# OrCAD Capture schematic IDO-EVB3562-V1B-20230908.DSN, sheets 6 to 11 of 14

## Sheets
6 P16.VI-Camera_MIPI_CSI: size A3; title: IDO-SBC3566-V1B; note: VI-Camera_MIPI_CSI
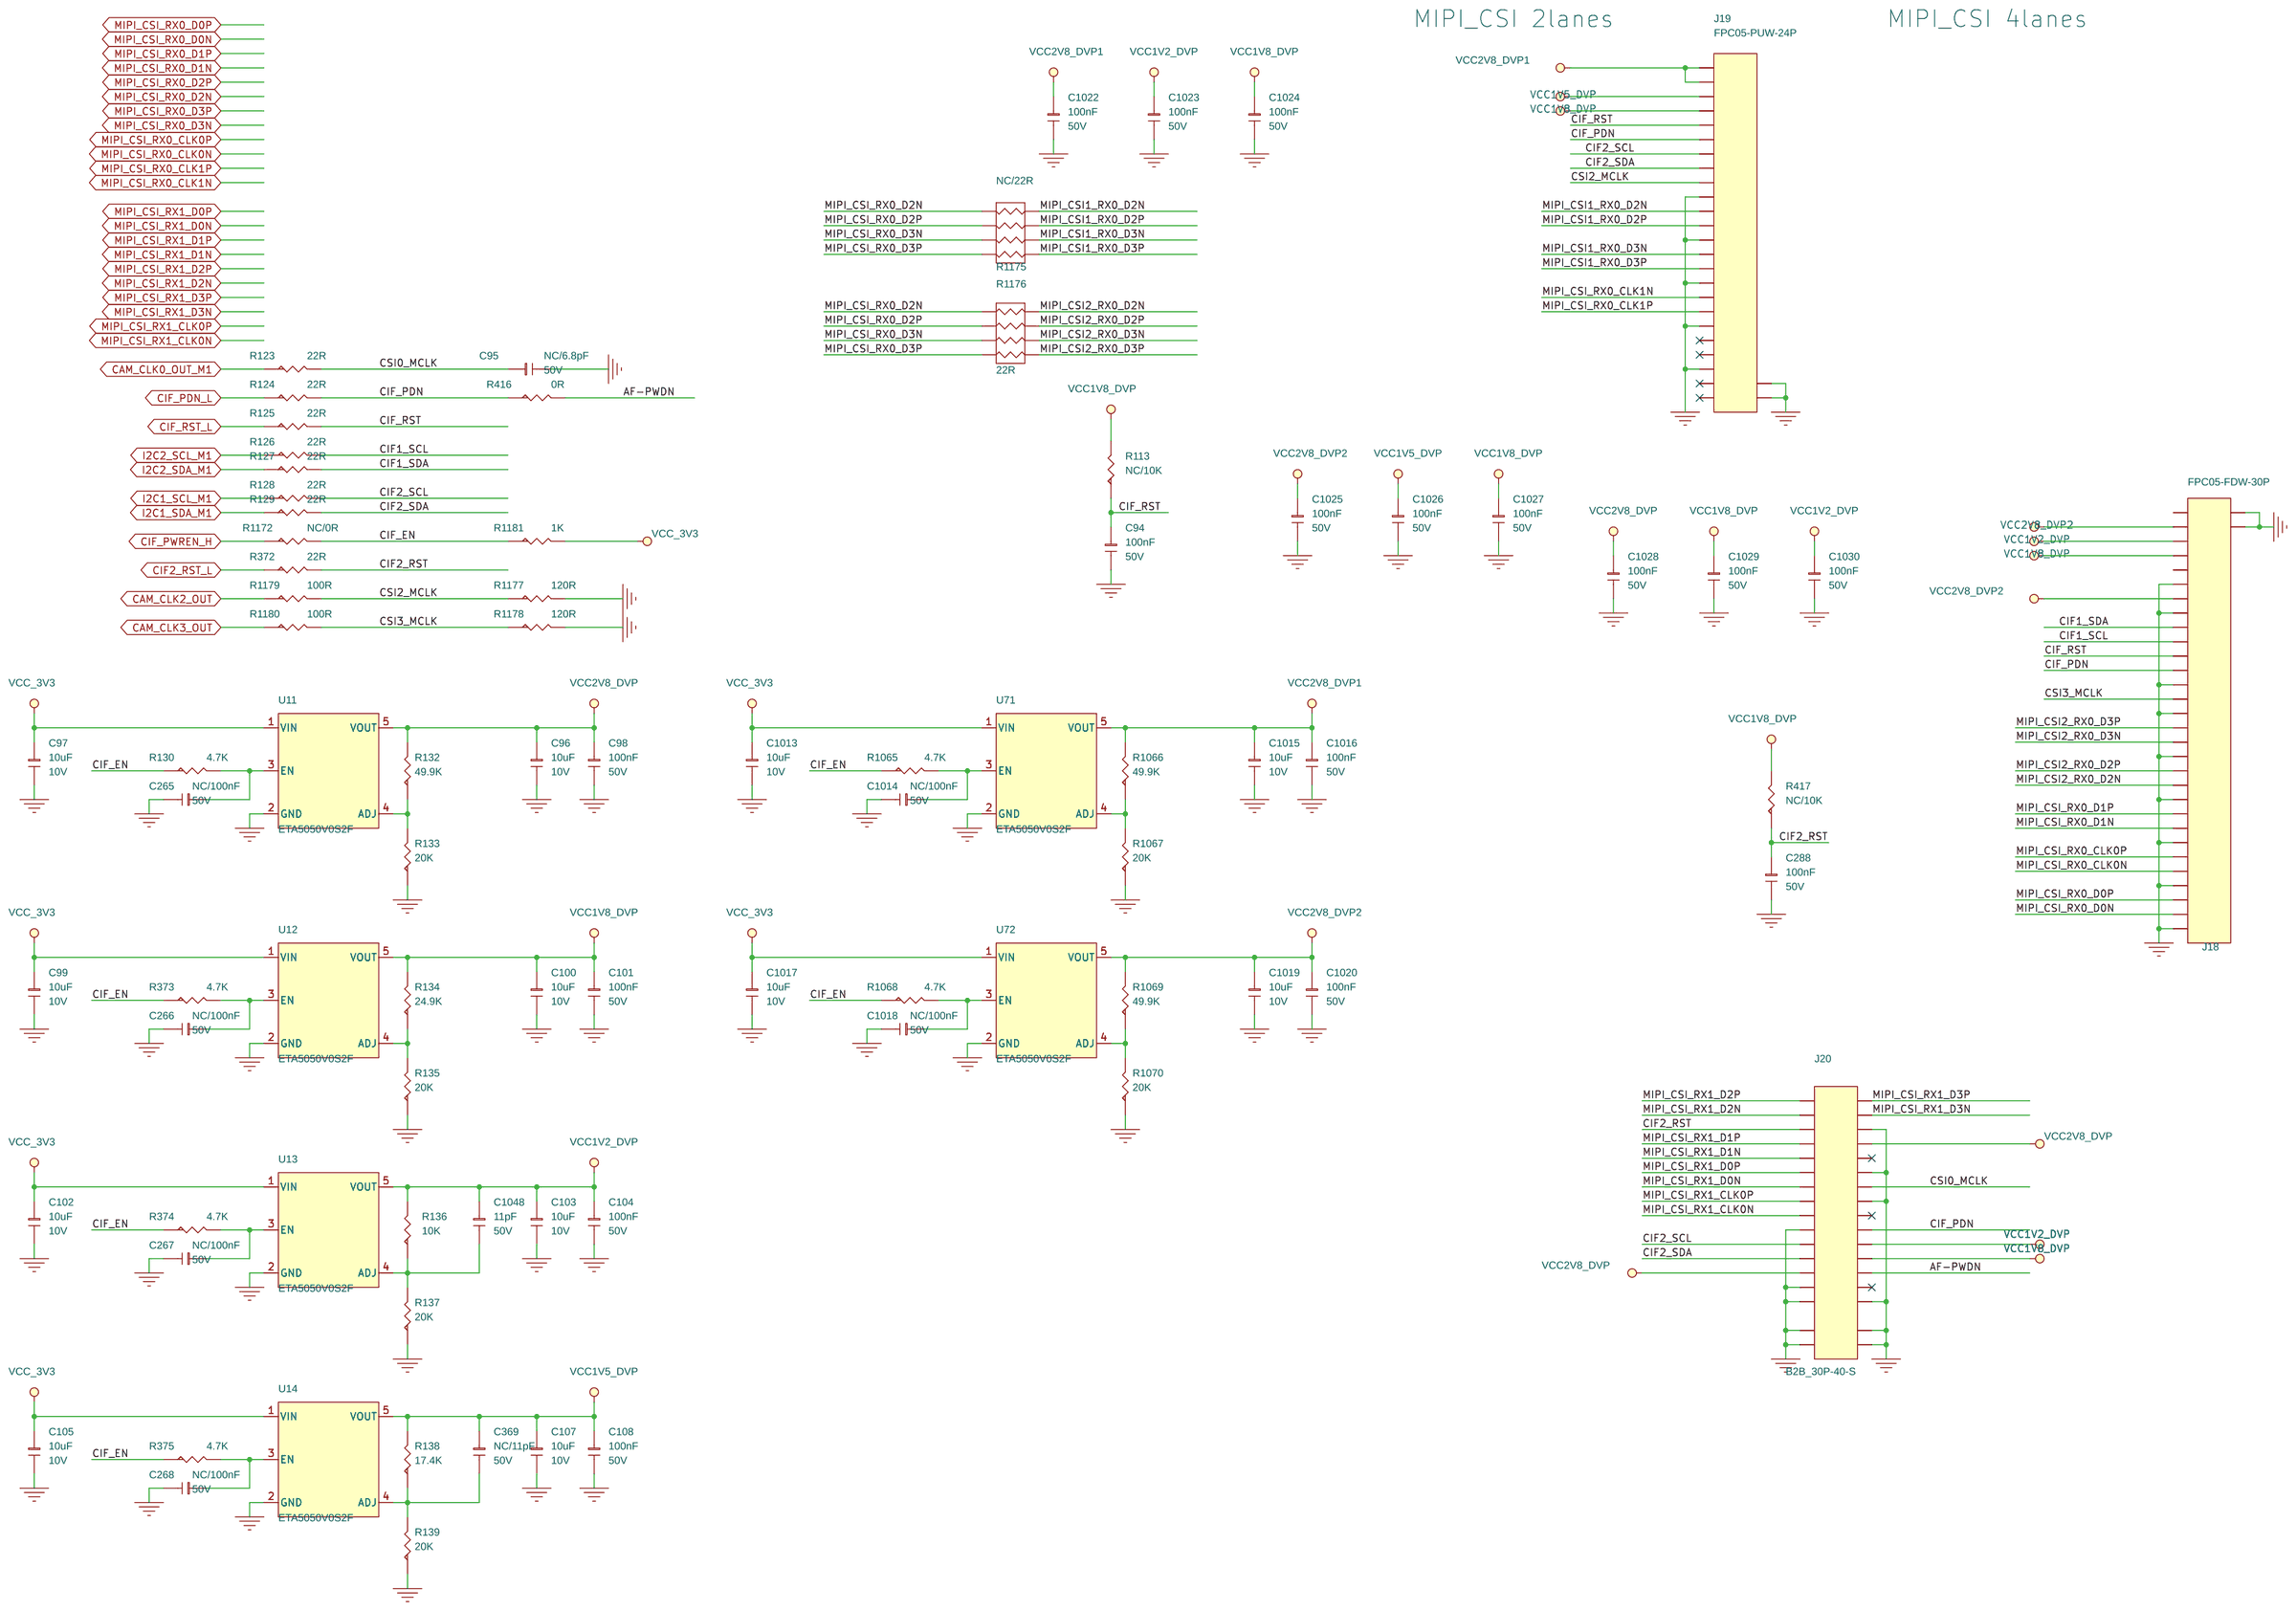
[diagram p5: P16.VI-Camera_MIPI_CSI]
7 P17.Ethernet2-PCIE: size A3; title: IDO-EVB3588-V1; note: Ethernet2-PCIE
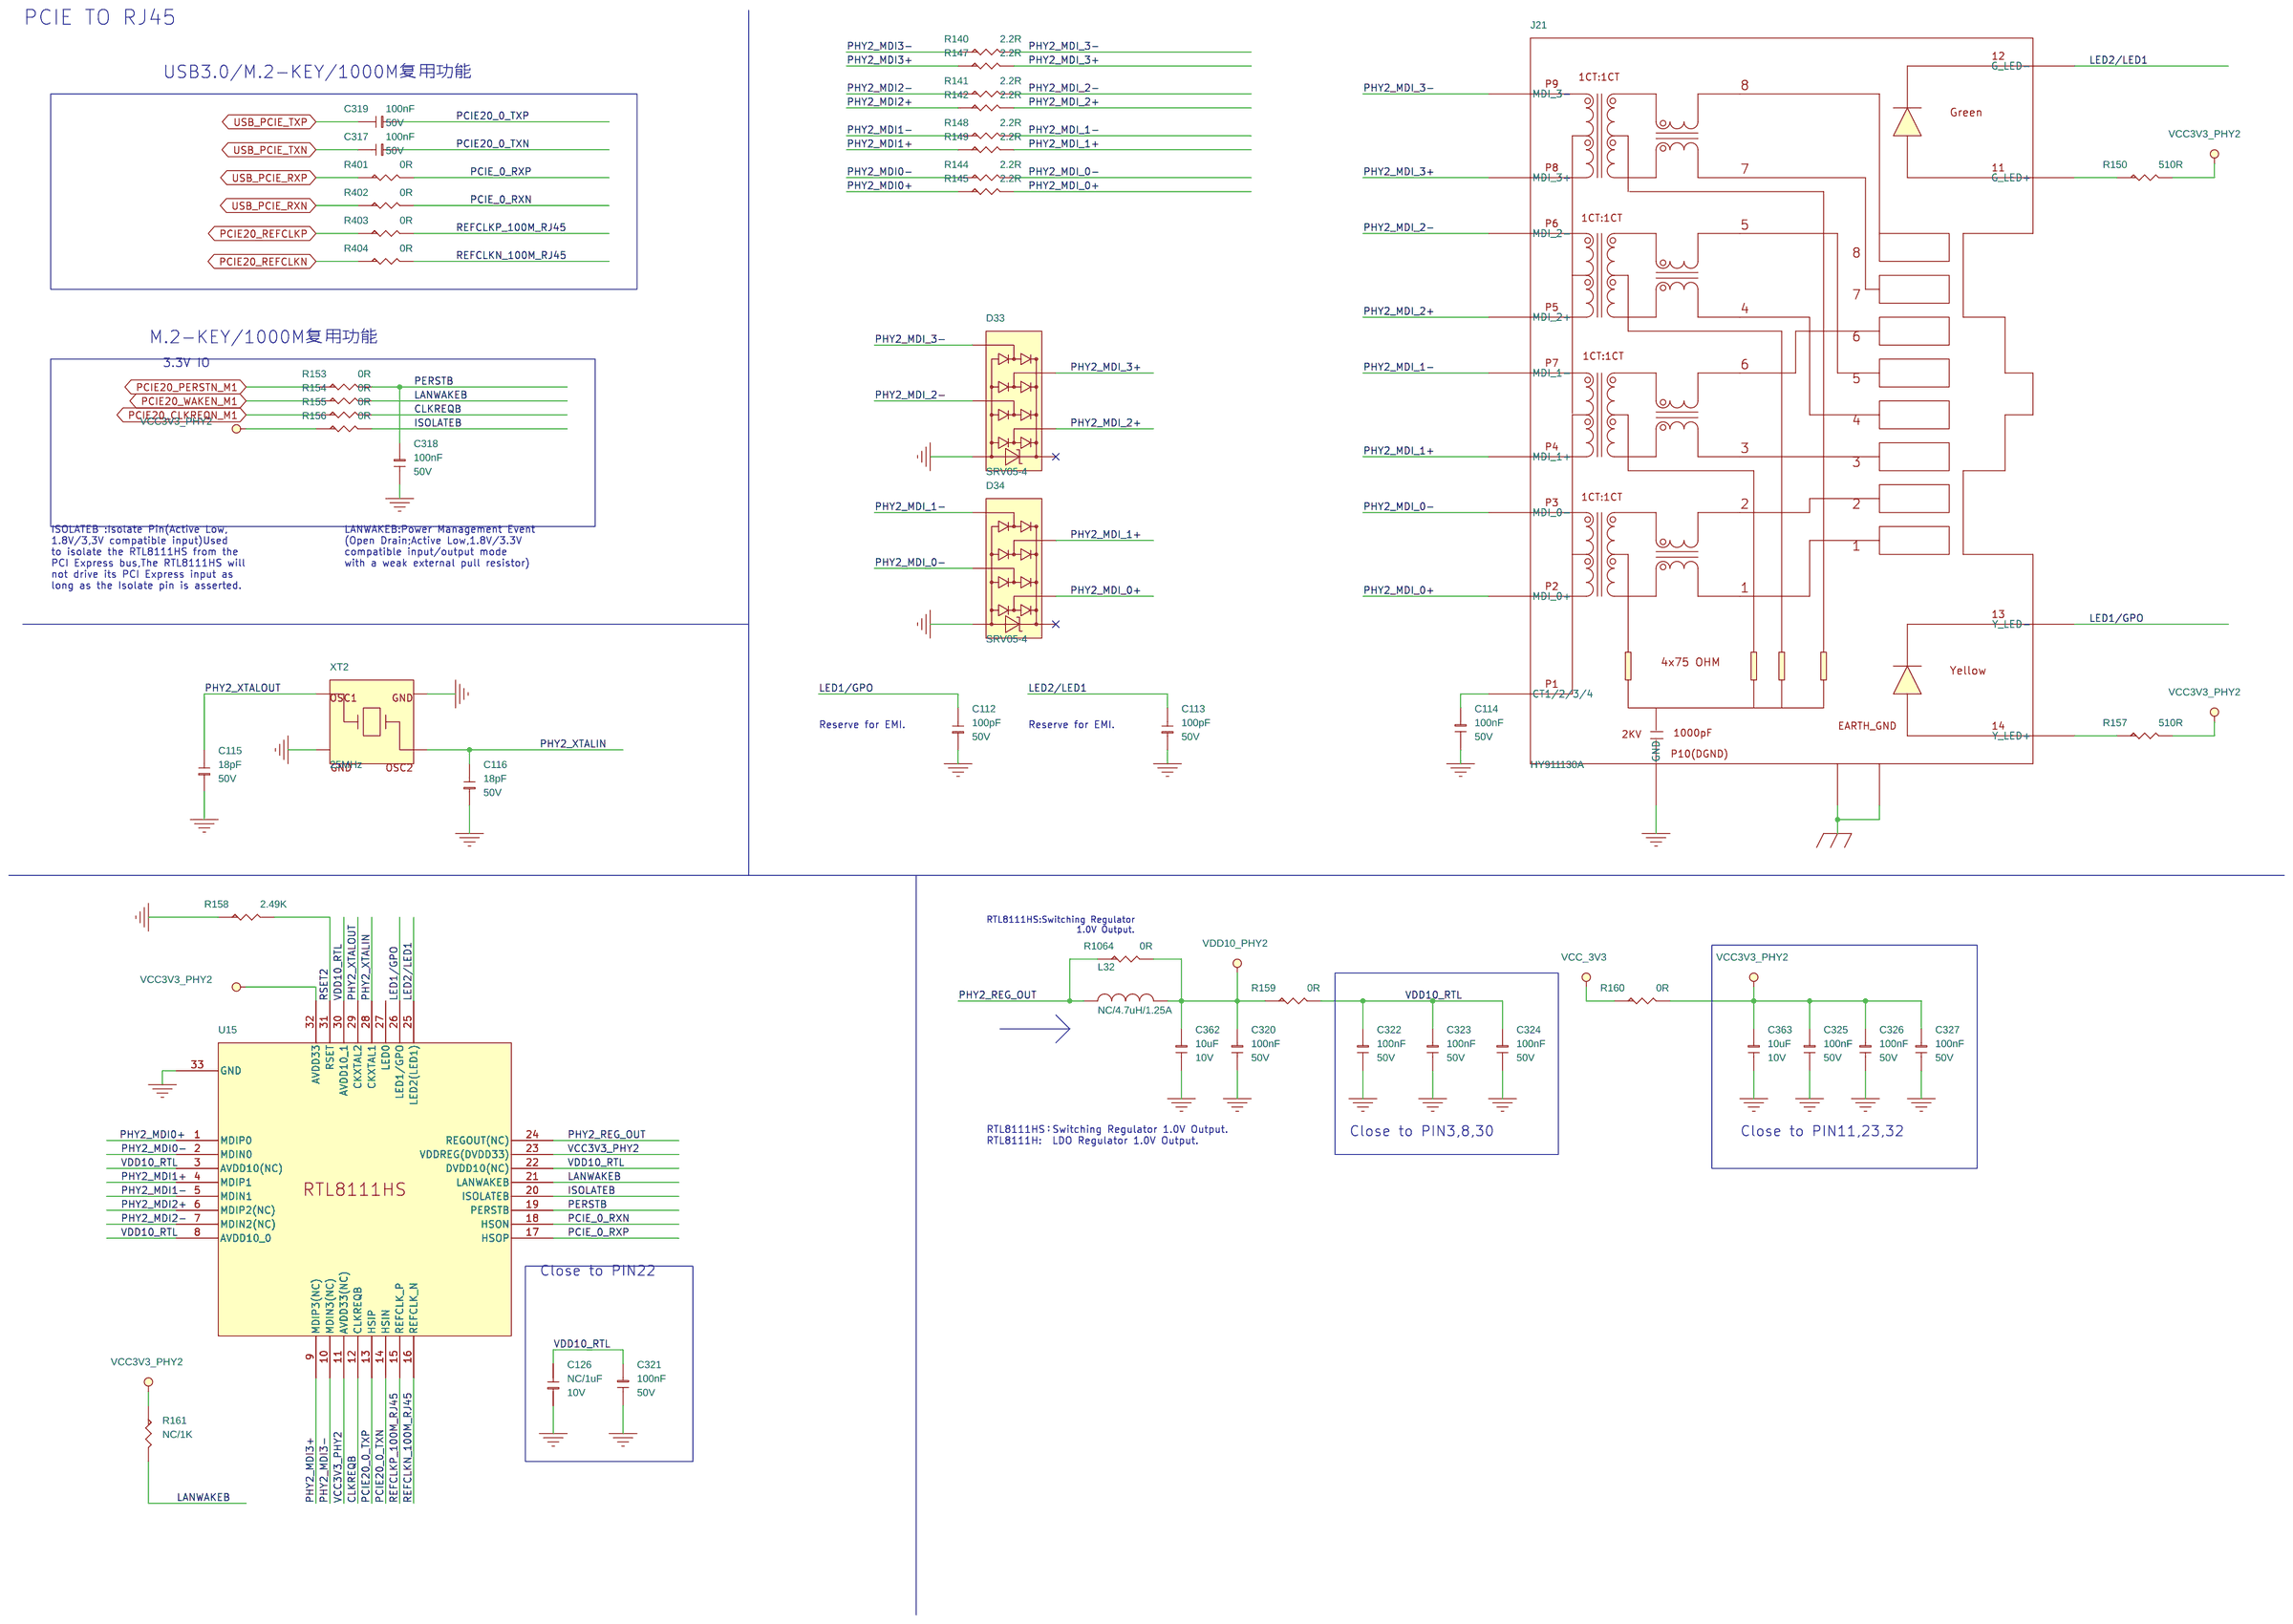
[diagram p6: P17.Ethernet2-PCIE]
8 P18. Ethernet-GEPHY_RGMII: size A2; title: IDO-SBC3566-V1B; note: Ethernet-GEPHY_RGMII
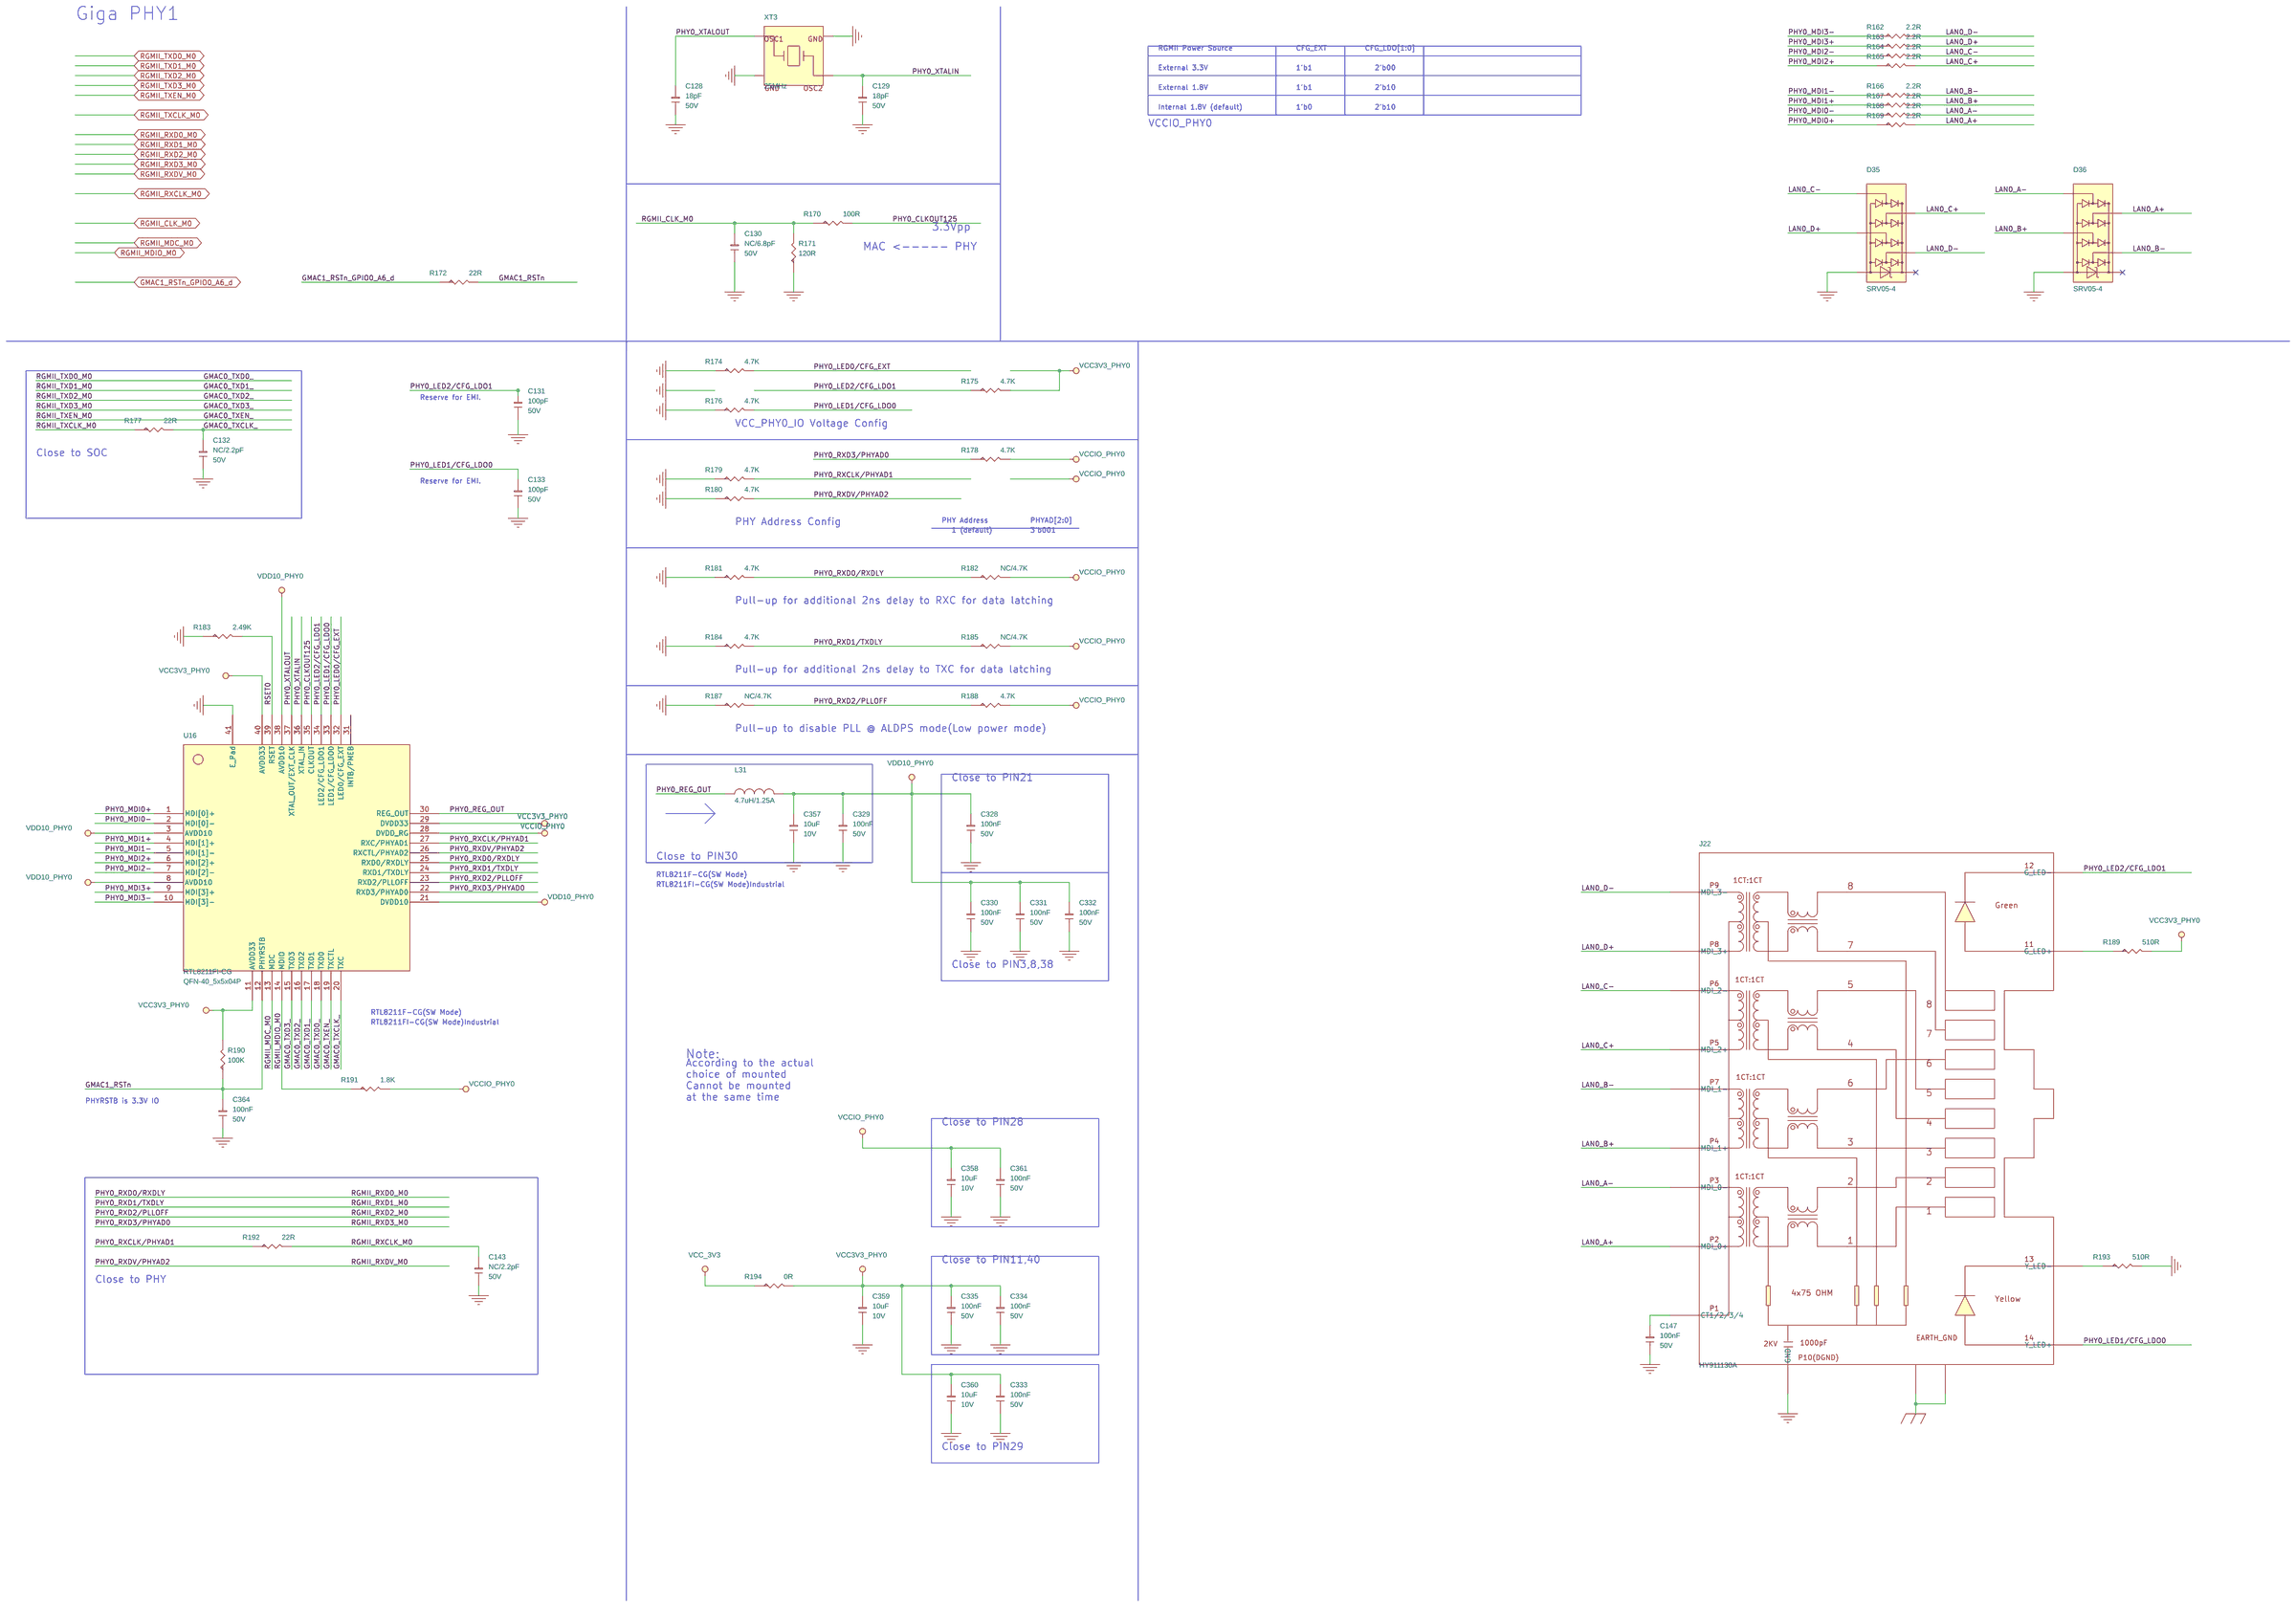
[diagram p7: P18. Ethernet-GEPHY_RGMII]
9 P30.IO/ADC: size A4; title: IDO-SBC3566-V1B; note: TP_Connector-COF/Backlight
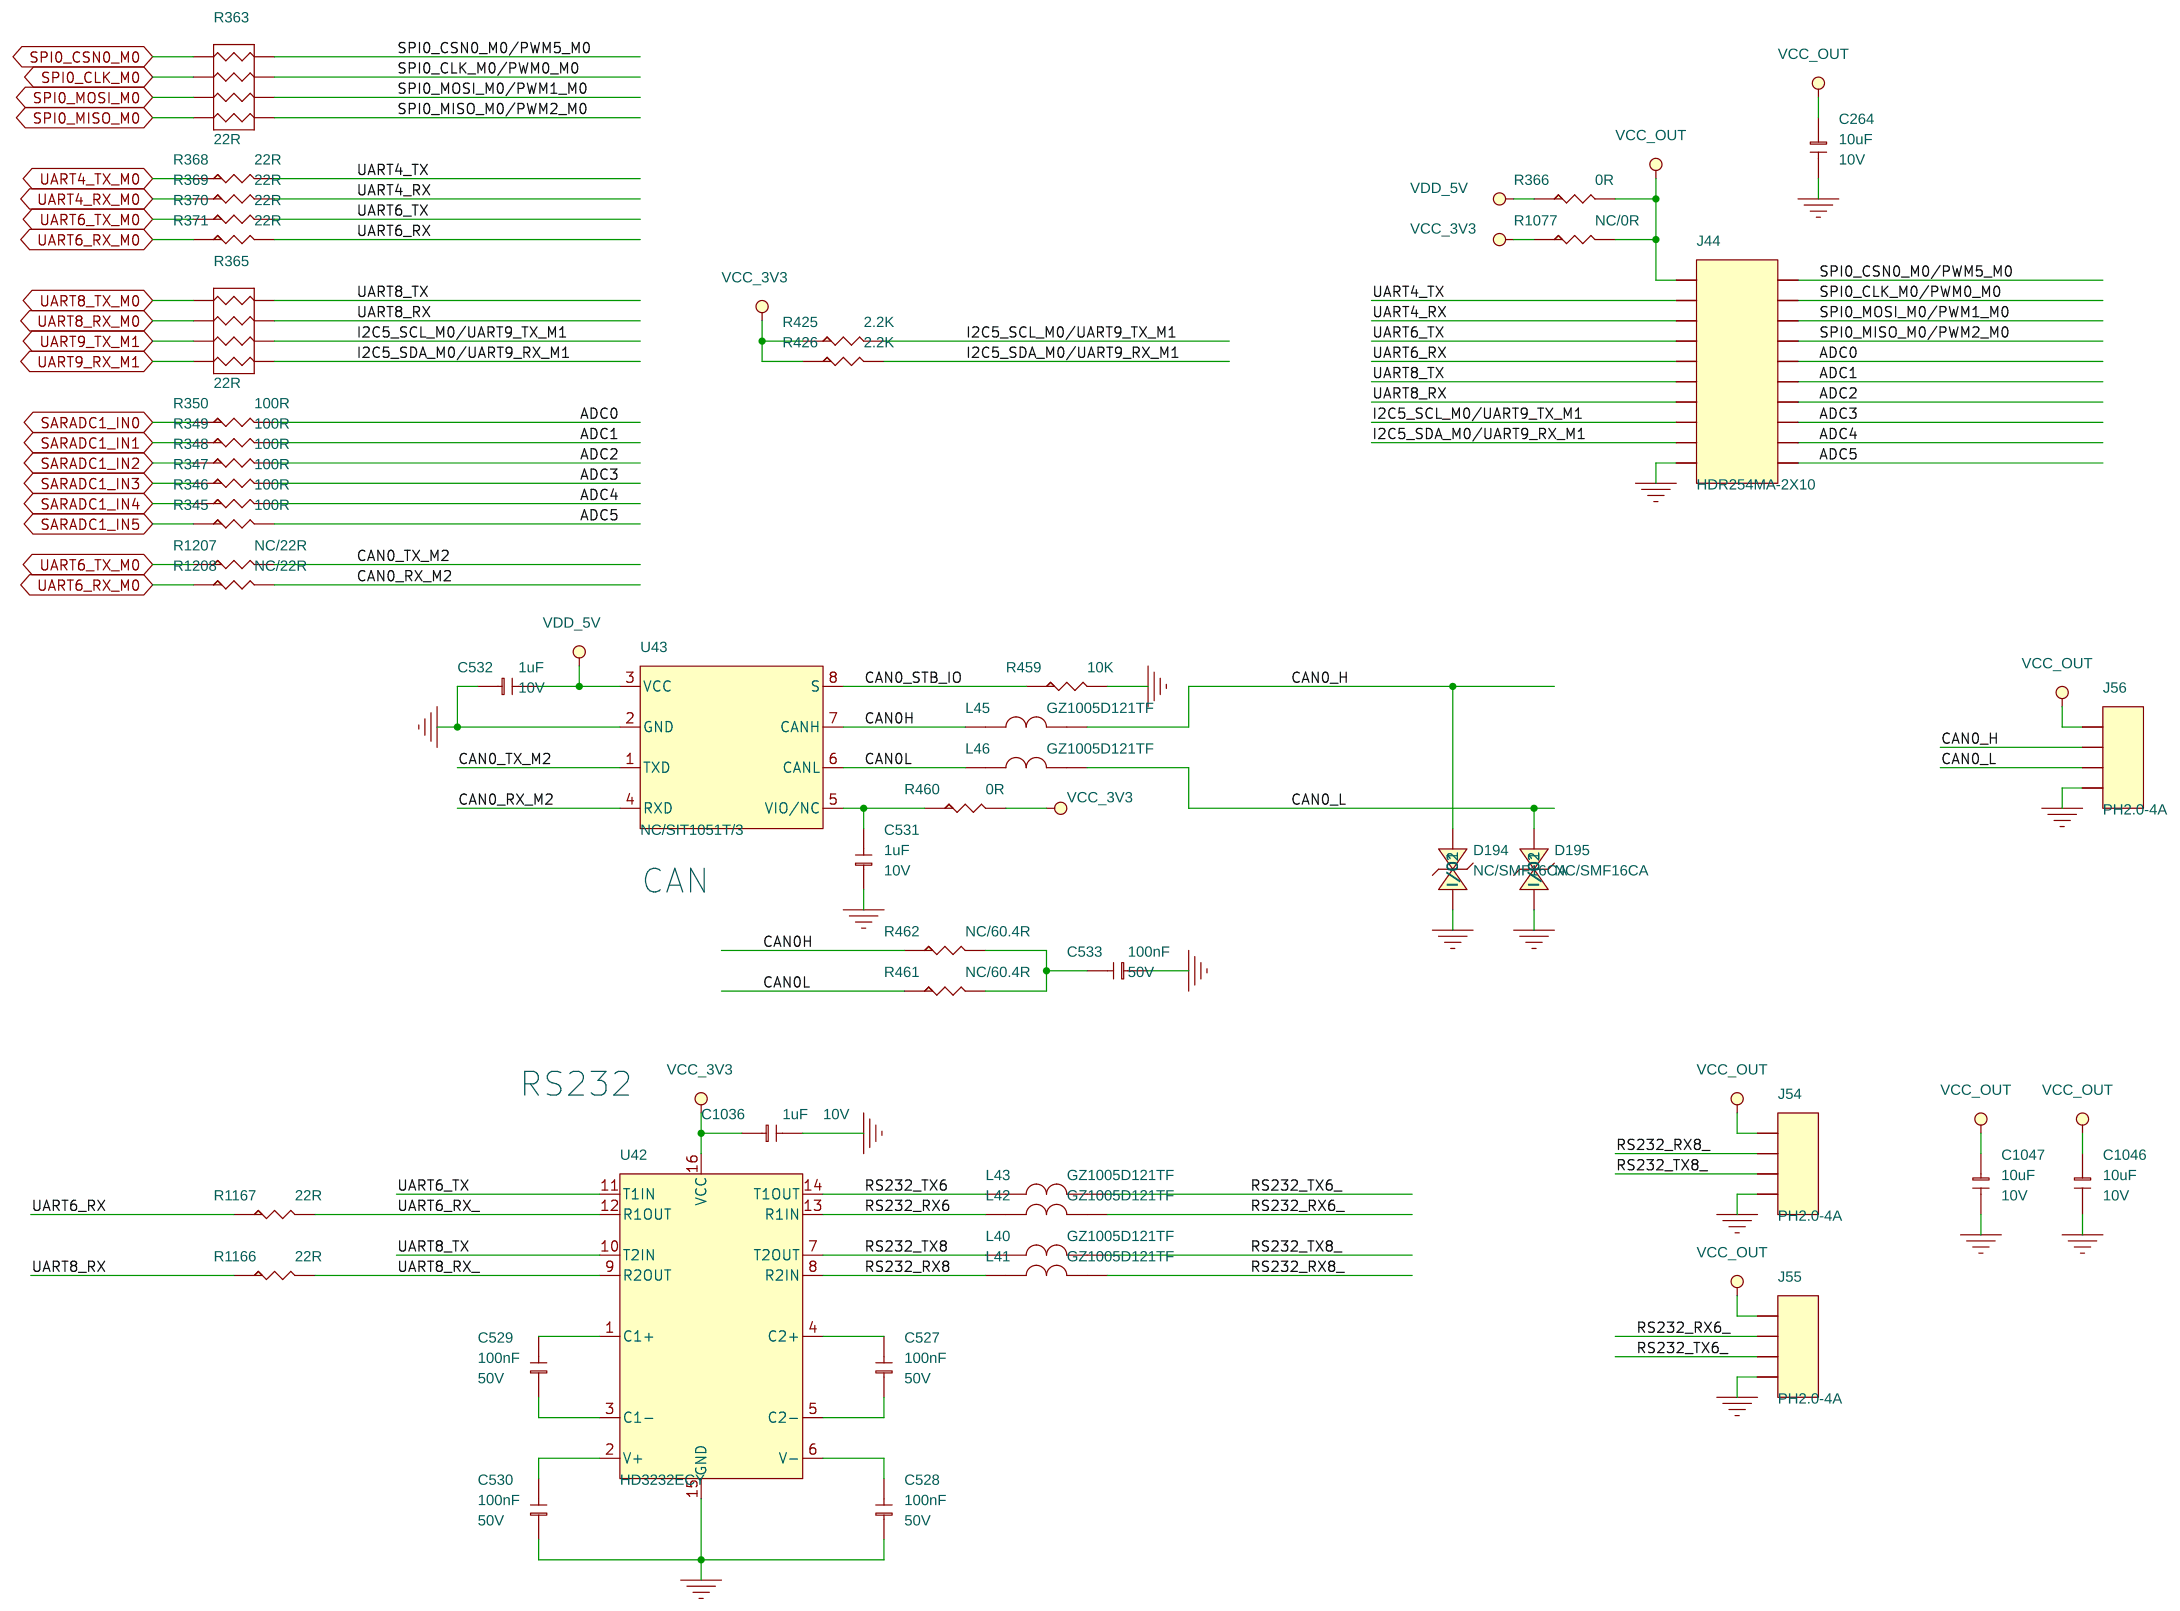
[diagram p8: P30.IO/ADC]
10 P21. USB3.0/M.2: size A3
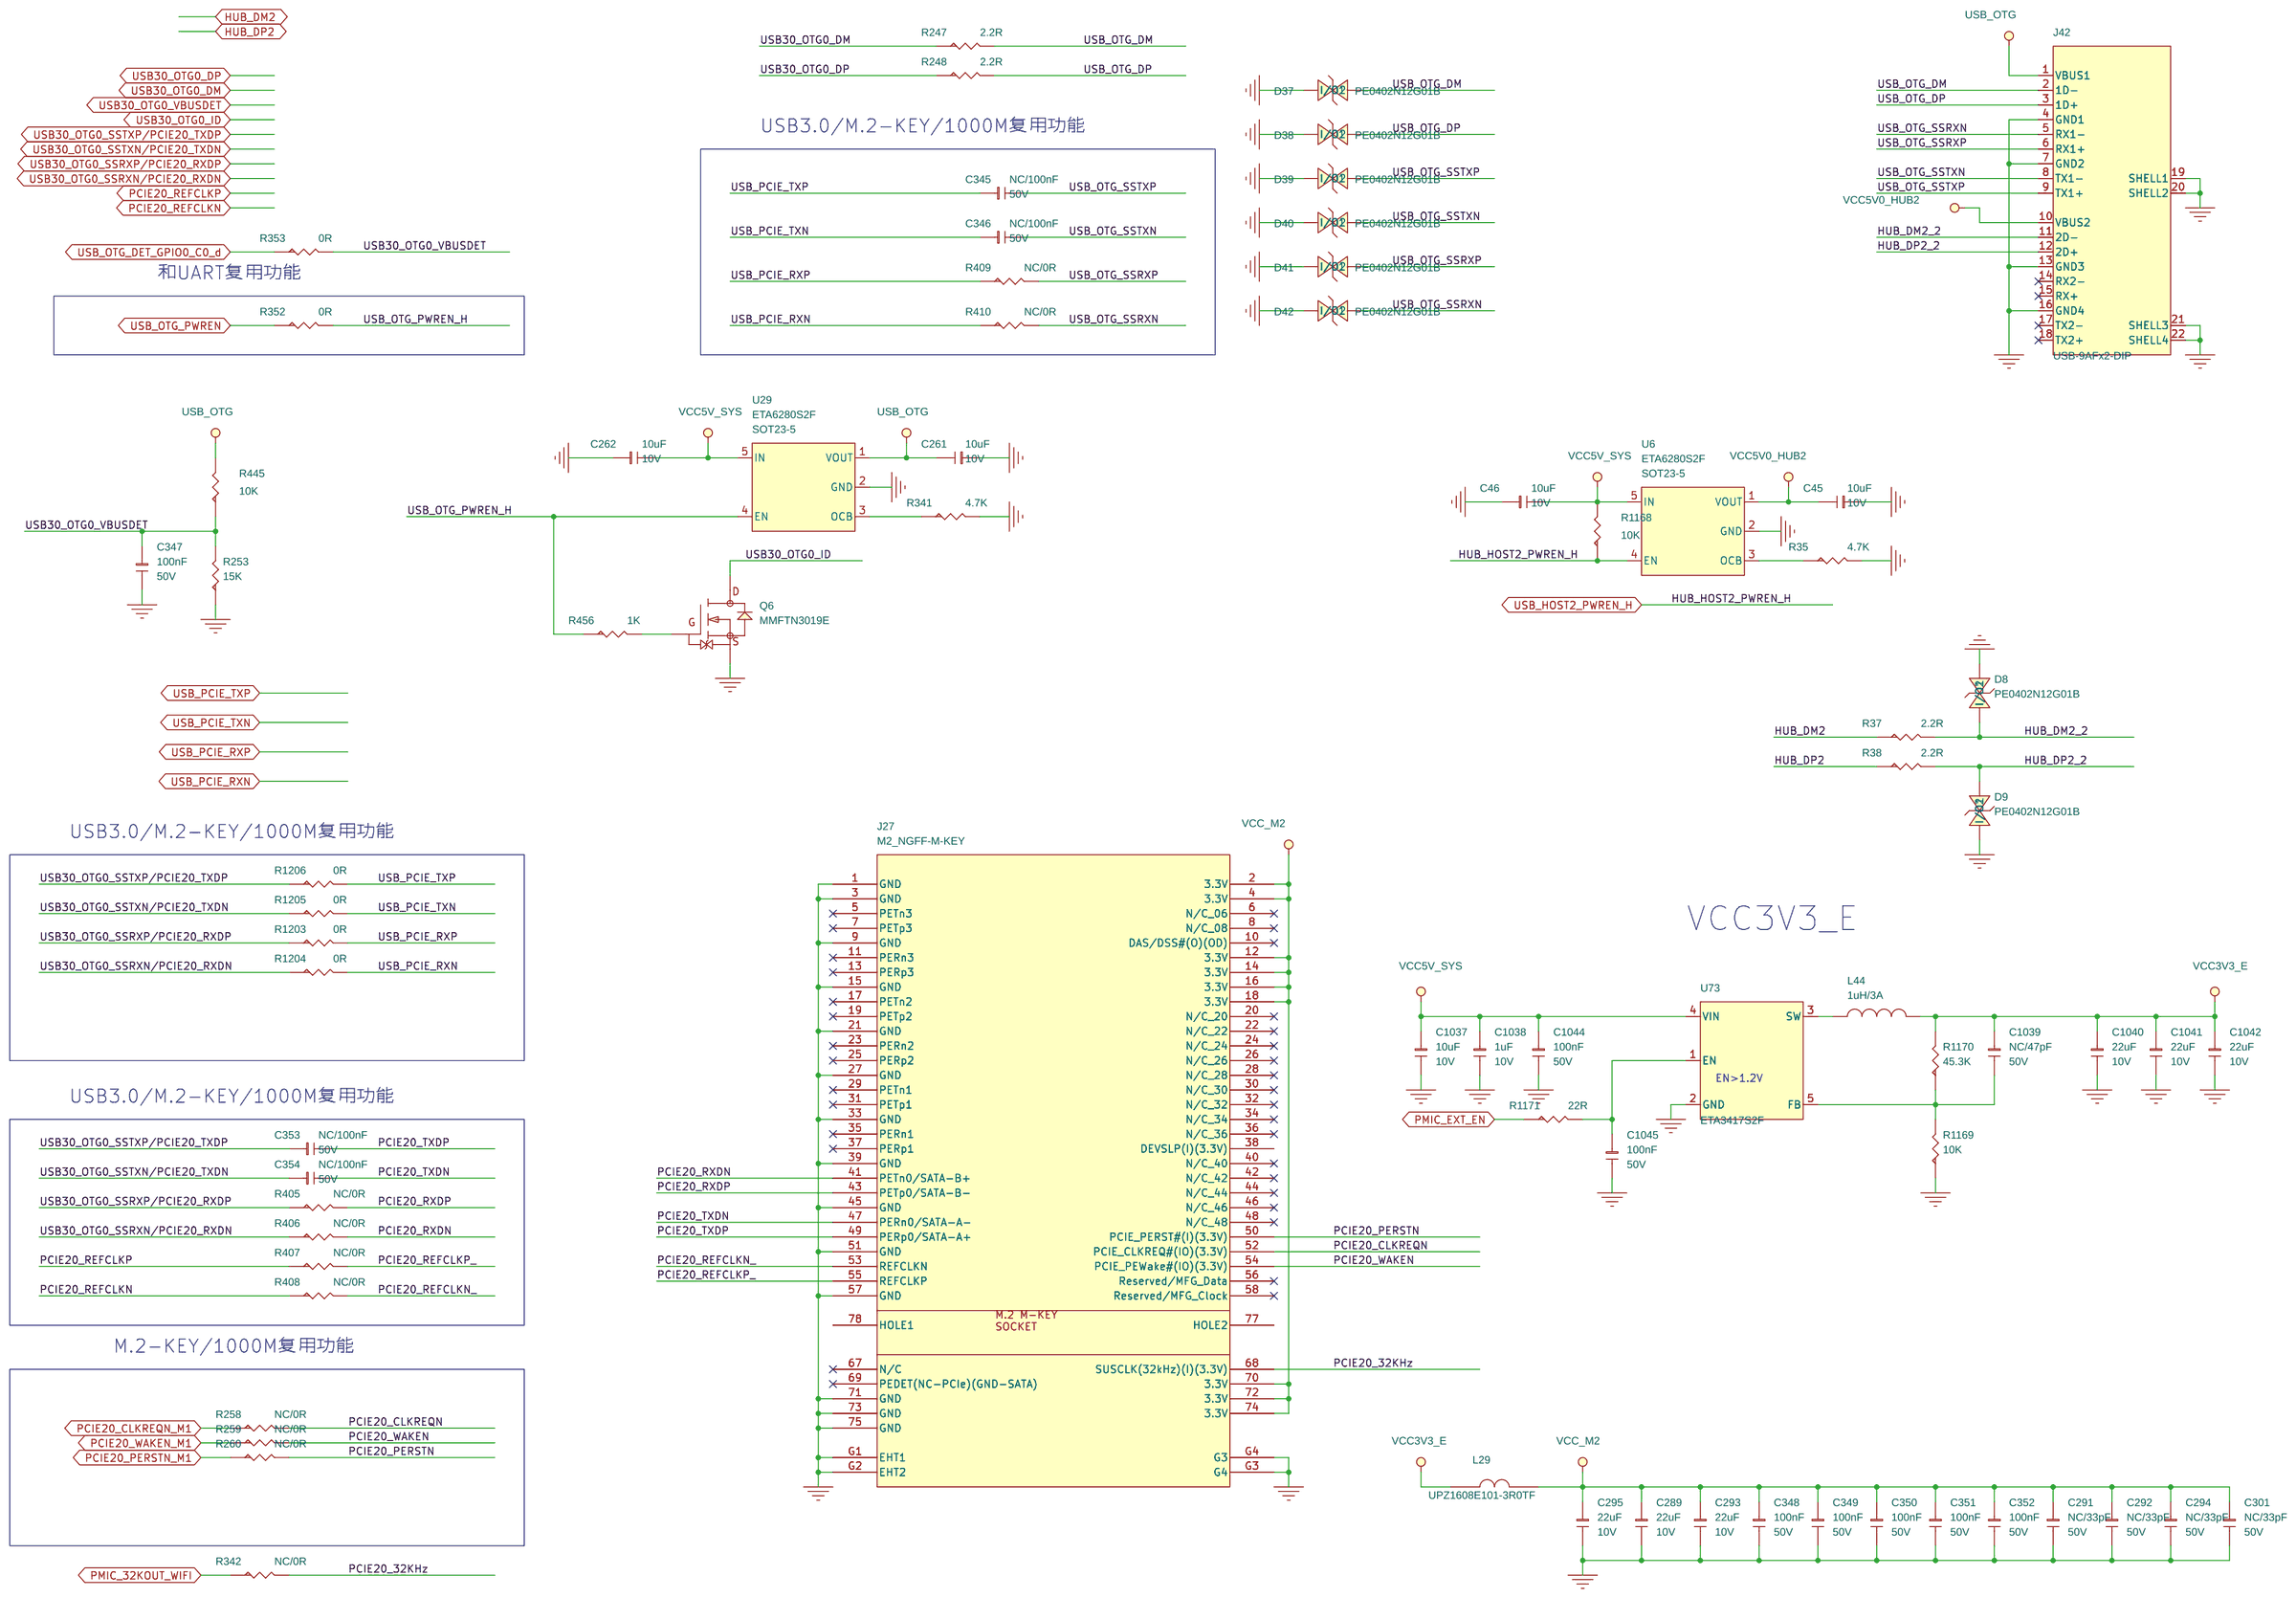
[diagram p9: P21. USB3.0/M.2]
11 P19.10/100M Ethernet: size A3; title: IDO-CTB3020; rev: 1.0; note: 8201F-RJ45
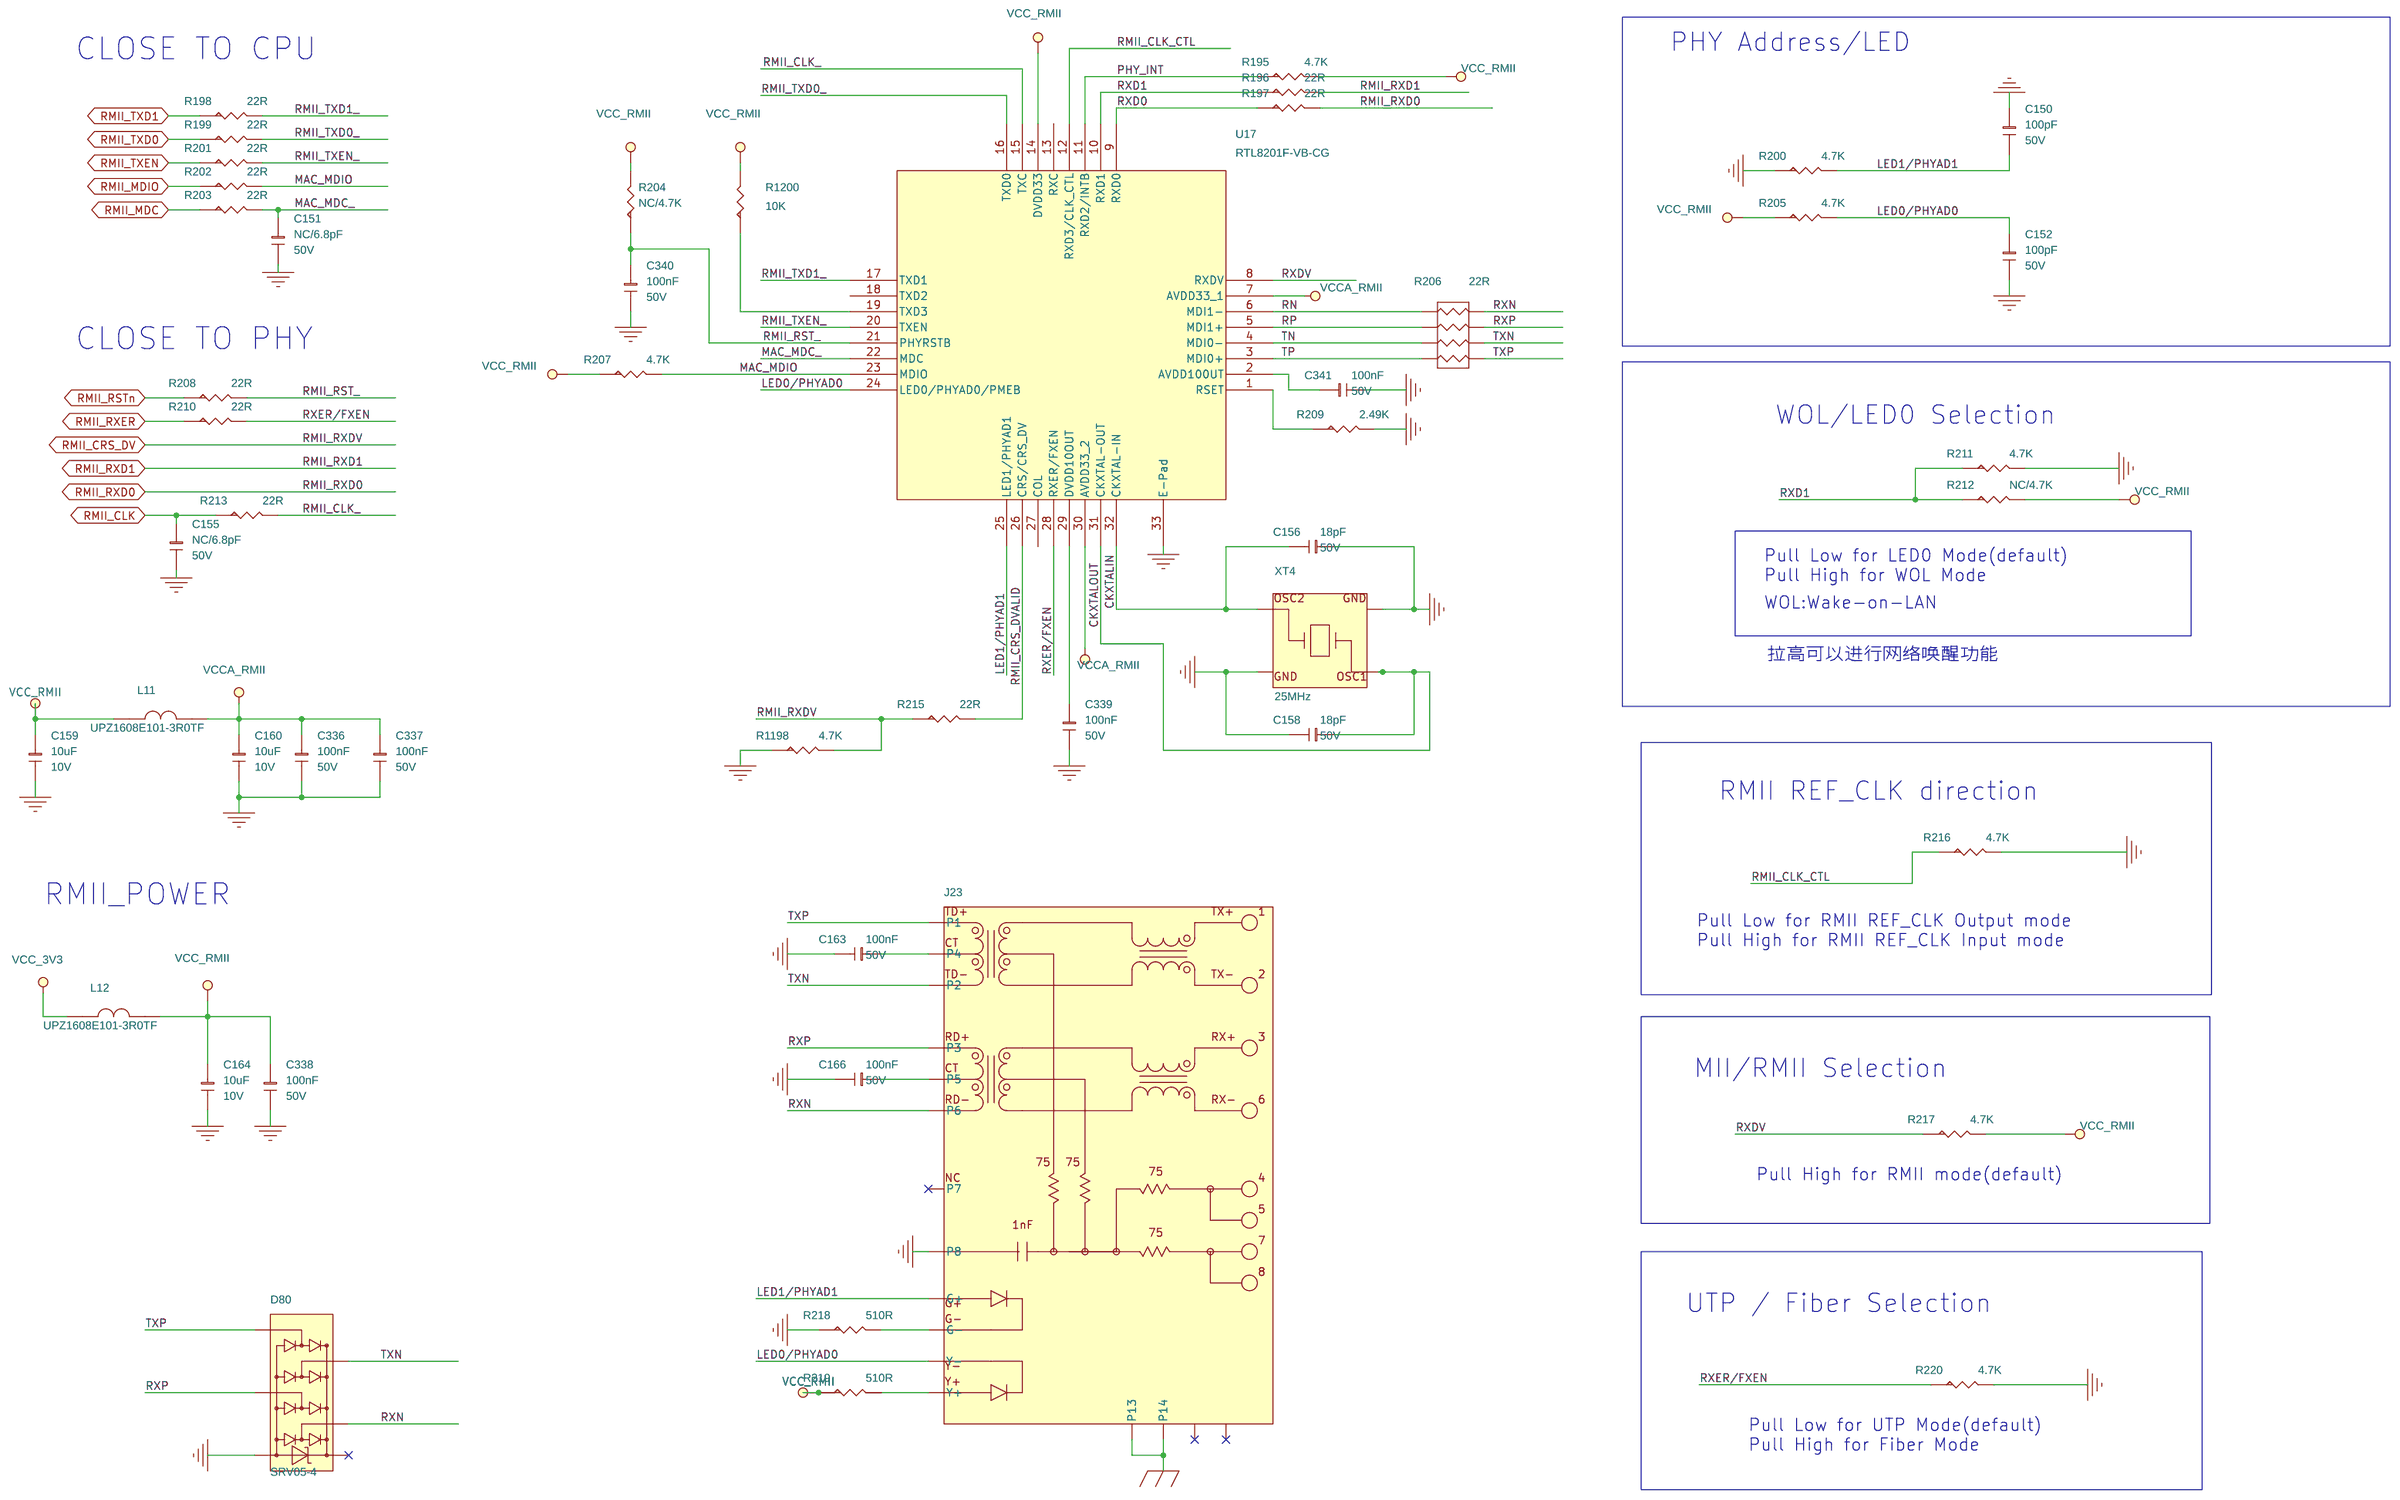
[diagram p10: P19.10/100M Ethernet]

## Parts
sheet P16.VI-Camera_MIPI_CSI
C94  100nF  [C0402]
C95  NC/6.8pF  [C0402]
C96  10uF  [C0603]
C97  10uF  [C0603]
C98  100nF  [C0402]
C99  10uF  [C0603]
C100  10uF  [C0603]
C101  100nF  [C0402]
C102  10uF  [C0603]
C103  10uF  [C0603]
C104  100nF  [C0402]
C105  10uF  [C0603]
C107  10uF  [C0603]
C108  100nF  [C0402]
C265  NC/100nF  [C0402]
C266  NC/100nF  [C0402]
C267  NC/100nF  [C0402]
C268  NC/100nF  [C0402]
C288  100nF  [C0402]
C369  NC/11pF  [C0402]
C1013  10uF  [C0603]
C1014  NC/100nF  [C0402]
C1015  10uF  [C0603]
C1016  100nF  [C0402]
C1017  10uF  [C0603]
C1018  NC/100nF  [C0402]
C1019  10uF  [C0603]
C1020  100nF  [C0402]
C1022  100nF  [C0402]
C1023  100nF  [C0402]
C1024  100nF  [C0402]
C1025  100nF  [C0402]
C1026  100nF  [C0402]
C1027  100nF  [C0402]
C1028  100nF  [C0402]
C1029  100nF  [C0402]
C1030  100nF  [C0402]
C1048  11pF  [C0402]
J18  FPC05-FDW-30P  [FPC05-30P]
J19  FPC05-PUW-24P  [FPC05-24P]
J20  B2B_30P-40-S  [B2B_30P-40-S]
R113  NC/10K  [R0402]
R123  22R  [R0402]
R124  22R  [R0402]
R125  22R  [R0402]
R126  22R  [R0402]
R127  22R  [R0402]
R128  22R  [R0402]
R129  22R  [R0402]
R130  4.7K  [R0402]
R132  49.9K  [R0402]
R133  20K  [R0402]
R134  24.9K  [R0402]
R135  20K  [R0402]
R136  10K  [R0402]
R137  20K  [R0402]
R138  17.4K  [R0402]
R139  20K  [R0402]
R372  22R  [R0402]
R373  4.7K  [R0402]
R374  4.7K  [R0402]
R375  4.7K  [R0402]
R416  0R  [R0402]
R417  NC/10K  [R0402]
R1065  4.7K  [R0402]
R1066  49.9K  [R0402]
R1067  20K  [R0402]
R1068  4.7K  [R0402]
R1069  49.9K  [R0402]
R1070  20K  [R0402]
R1172  NC/0R  [R0402]
R1175  NC/22R  [RN_0402X4]
R1176  22R  [RN_0402X4]
R1177  120R  [R0402]
R1178  120R  [R0402]
R1179  100R  [R0402]
R1180  100R  [R0402]
R1181  1K  [R0402]
U11  ETA5050V0S2F  [SOT23-5]
U12  ETA5050V0S2F  [SOT23-5]
U13  ETA5050V0S2F  [SOT23-5]
U14  ETA5050V0S2F  [SOT23-5]
U71  ETA5050V0S2F  [SOT23-5]
U72  ETA5050V0S2F  [SOT23-5]
sheet P17.Ethernet2-PCIE
C112  100pF  [C0402]
C113  100pF  [C0402]
C114  100nF  [C0402]
C115  18pF  [C0402]
C116  18pF  [C0402]
C126  NC/1uF  [C0402]
C317  100nF  [C0402]
C318  100nF  [C0402]
C319  100nF  [C0402]
C320  100nF  [C0402]
C321  100nF  [C0402]
C322  100nF  [C0402]
C323  100nF  [C0402]
C324  100nF  [C0402]
C325  100nF  [C0402]
C326  100nF  [C0402]
C327  100nF  [C0402]
C362  10uF  [C0603]
C363  10uF  [C0603]
D33  SRV05-4  [SOT23-6]
D34  SRV05-4  [SOT23-6]
J21  HY911130A  [RJ45-TH_HY911130A]
L32  NC/4.7uH/1.25A  [IND_252012]
R140  2.2R  [R0402]
R141  2.2R  [R0402]
R142  2.2R  [R0402]
R144  2.2R  [R0402]
R145  2.2R  [R0402]
R147  2.2R  [R0402]
R148  2.2R  [R0402]
R149  2.2R  [R0402]
R150  510R  [R0402]
R153  0R  [R0402]
R154  0R  [R0402]
R155  0R  [R0402]
R156  0R  [R0402]
R157  510R  [R0402]
R158  2.49K  [R0402]
R159  0R  [R0402]
R160  0R  [R0402]
R161  NC/1K  [R0402]
R401  0R  [R0402]
R402  0R  [R0402]
R403  0R  [R0402]
R404  0R  [R0402]
R1064  0R  [R0805]
U15  RTL8111HS  [QFN-32_4x4x04P]
XT2  25MHz  [xtal_32x25_4p]
sheet P18. Ethernet-GEPHY_RGMII
C128  18pF  [C0402]
C129  18pF  [C0402]
C130  NC/6.8pF  [C0402]
C131  100pF  [C0402]
C132  NC/2.2pF  [C0402]
C133  100pF  [C0402]
C143  NC/2.2pF  [C0402]
C147  100nF  [C0402]
C328  100nF  [C0402]
C329  100nF  [C0402]
C330  100nF  [C0402]
C331  100nF  [C0402]
C332  100nF  [C0402]
C333  100nF  [C0402]
C334  100nF  [C0402]
C335  100nF  [C0402]
C357  10uF  [C0603]
C358  10uF  [C0603]
C359  10uF  [C0603]
C360  10uF  [C0603]
C361  100nF  [C0402]
C364  100nF  [C0402]
D35  SRV05-4  [SOT23-6]
D36  SRV05-4  [SOT23-6]
J22  HY911130A  [RJ45-TH_HY911130A]
L31  4.7uH/1.25A  [IND_252012]
R162  2.2R  [R0402]
R163  2.2R  [R0402]
R164  2.2R  [R0402]
R165  2.2R  [R0402]
R166  2.2R  [R0402]
R167  2.2R  [R0402]
R168  2.2R  [R0402]
R169  2.2R  [R0402]
R170  100R  [R0402]
R171  120R  [R0402]
R172  22R  [R0402]
R174  4.7K  [R0402]
R175  4.7K  [R0402]
R176  4.7K  [R0402]
R177  22R  [R0402]
R178  4.7K  [R0402]
R179  4.7K  [R0402]
R180  4.7K  [R0402]
R181  4.7K  [R0402]
R182  NC/4.7K  [R0402]
R183  2.49K  [R0402]
R184  4.7K  [R0402]
R185  NC/4.7K  [R0402]
R187  NC/4.7K  [R0402]
R188  4.7K  [R0402]
R189  510R  [R0402]
R190  100K  [R0402]
R191  1.8K  [R0402]
R192  22R  [R0402]
R193  510R  [R0402]
R194  0R  [R0402]
U16  RTL8211FI-CG  [QFN-40_5x5x04P]
XT3  25MHz  [xtal_32x25_4p]
sheet P19.10/100M Ethernet
C150  100pF  [C0402]
C151  NC/6.8pF  [C0402]
C152  100pF  [C0402]
C155  NC/6.8pF  [C0402]
C156  18pF  [C0402]
C158  18pF  [C0402]
C159  10uF  [C0603]
C160  10uF  [C0603]
C163  100nF  [C0402]
C164  10uF  [C0603]
C166  100nF  [C0402]
C336  100nF  [C0402]
C337  100nF  [C0402]
C338  100nF  [C0402]
C339  100nF  [C0402]
C340  100nF  [C0402]
C341  100nF  [C0402]
D80  SRV05-4  [SOT23-6]
J23  HR911105A  [RJ45-TH_HR911105A]
L11  UPZ1608E101-3R0TF  [L0603]
L12  UPZ1608E101-3R0TF  [L0603]
R195  4.7K  [R0402]
R196  22R  [R0402]
R197  22R  [R0402]
R198  22R  [R0402]
R199  22R  [R0402]
R200  4.7K  [R0402]
R201  22R  [R0402]
R202  22R  [R0402]
R203  22R  [R0402]
R204  NC/4.7K  [R0402]
R205  4.7K  [R0402]
R206  22R  [RN_0402X4]
R207  4.7K  [R0402]
R208  22R  [R0402]
R209  2.49K  [R0402]
R210  22R  [R0402]
R211  4.7K  [R0402]
R212  NC/4.7K  [R0402]
R213  22R  [R0402]
R215  22R  [R0402]
R216  4.7K  [R0402]
R217  4.7K  [R0402]
R218  510R  [R0402]
R219  510R  [R0402]
R220  4.7K  [R0402]
R1198  4.7K  [R0402]
R1200  10K  [R0402]
U17  RTL8201F-VB-CG  [QFN-32_5x5x05P]
XT4  25MHz  [xtal_32x25_4p]
sheet P21. USB3.0/M.2
C45  10uF  [C0603]
C46  10uF  [C0603]
C261  10uF  [C0603]
C262  10uF  [C0603]
C289  22uF  [C0603]
C291  NC/33pF  [C0402]
C292  NC/33pF  [C0402]
C293  22uF  [C0603]
C294  NC/33pF  [C0402]
C295  22uF  [C0603]
C301  NC/33pF  [C0402]
C345  NC/100nF  [C0402]
C346  NC/100nF  [C0402]
C347  100nF  [C0402]
C348  100nF  [C0402]
C349  100nF  [C0402]
C350  100nF  [C0402]
C351  100nF  [C0402]
C352  100nF  [C0402]
C353  NC/100nF  [C0402]
C354  NC/100nF  [C0402]
C1037  10uF  [C0603]
C1038  1uF  [C0402]
C1039  NC/47pF  [C0402]
C1040  22uF  [C0603]
C1041  22uF  [C0603]
C1042  22uF  [C0603]
C1044  100nF  [C0402]
C1045  100nF  [C0402]
D8  PE0402N12G01B  [V0402]
D9  PE0402N12G01B  [V0402]
D37  PE0402N12G01B  [V0402]
D38  PE0402N12G01B  [V0402]
D39  PE0402N12G01B  [V0402]
D40  PE0402N12G01B  [V0402]
D41  PE0402N12G01B  [V0402]
D42  PE0402N12G01B  [V0402]
J27  M2_NGFF-M-KEY  [M2_NGFF-M-KEY]
J42  USB-9AFx2-DIP  [USB-9AF-DIP_2x]
L29  UPZ1608E101-3R0TF  [L0603]
L44  1uH/3A  [IND_252012]
Q6  MMFTN3019E  [SOT523]
R35  4.7K  [R0402]
R37  2.2R  [R0402]
R38  2.2R  [R0402]
R247  2.2R  [R0402]
R248  2.2R  [R0402]
R253  15K  [R0402]
R258  NC/0R  [R0402]
R259  NC/0R  [R0402]
R260  NC/0R  [R0402]
R341  4.7K  [R0402]
R342  NC/0R  [R0402]
R352  0R  [R0402]
R353  0R  [R0402]
R405  NC/0R  [R0402]
R406  NC/0R  [R0402]
R407  NC/0R  [R0402]
R408  NC/0R  [R0402]
R409  NC/0R  [R0402]
R410  NC/0R  [R0402]
R445  10K  [R0402]
R456  1K  [R0402]
R1168  10K  [R0402]
R1169  10K  [R0402]
R1170  45.3K  [R0402]
R1171  22R  [R0402]
R1203  0R  [R0402]
R1204  0R  [R0402]
R1205  0R  [R0402]
R1206  0R  [R0402]
U6  ETA6280S2F  [SOT23-5]
U29  ETA6280S2F  [SOT23-5]
U73  ETA3417S2F  [SOT23-5]
sheet P30.IO/ADC
C264  10uF  [C0603]
C527  100nF  [C0402]
C528  100nF  [C0402]
C529  100nF  [C0402]
C530  100nF  [C0402]
C531  1uF  [C0402]
C532  1uF  [C0402]
C533  100nF  [C0402]
C1036  1uF  [C0402]
C1046  10uF  [C0603]
C1047  10uF  [C0603]
D194  NC/SMF16CA  [SOD-123F]
D195  NC/SMF16CA  [SOD-123F]
J44  HDR254MA-2X10  [HDR254MA-2X10]
J54  PH2.0-4A  [PH200-4A]
J55  PH2.0-4A  [PH200-4A]
J56  PH2.0-4A  [PH200-4A]
L40  GZ1005D121TF  [L0402]
L41  GZ1005D121TF  [L0402]
L42  GZ1005D121TF  [L0402]
L43  GZ1005D121TF  [L0402]
L45  GZ1005D121TF  [L0402]
L46  GZ1005D121TF  [L0402]
R345  100R  [R0402]
R346  100R  [R0402]
R347  100R  [R0402]
R348  100R  [R0402]
R349  100R  [R0402]
R350  100R  [R0402]
R363  22R  [RN_0402X4]
R365  22R  [RN_0402X4]
R366  0R  [R0402]
R368  22R  [R0402]
R369  22R  [R0402]
R370  22R  [R0402]
R371  22R  [R0402]
R425  2.2K  [R0402]
R426  2.2K  [R0402]
R459  10K  [R0402]
R460  0R  [R0402]
R461  NC/60.4R  [R0603]
R462  NC/60.4R  [R0603]
R1077  NC/0R  [R0402]
R1166  22R  [R0402]
R1167  22R  [R0402]
R1207  NC/22R  [R0402]
R1208  NC/22R  [R0402]
U42  HD3232ECY  [TSSOP-16]
U43  NC/SIT1051T/3  [SOP8-P127-390X490]

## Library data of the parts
C94 C98 C101 C104 C108 C114 C147 C163 C166 C265-C268 C288 C317-C341 C345-C354 C361 C364 C527-C530 C533 C1014 C1016 C1018 C1020 C1022-C1030 C1044 C1045 = C-0402: DSC1: ±10%; DSC2: 50V; DSC3: X7R; ERP Number: 1010200128; ID: 61; Manufacture: 三星|国巨|村田; Part Name: 贴片电容; Part Number: C020102120061; Price: 0.05
C95 C130 C151 C155 = C-0402: DSC1: ±0.25PF; DSC2: 50V; DSC3: C0G; ERP Number: 1010200056; ID: 18; Manufacture: 三星|国巨|村田; Part Name: 贴片电容; Part Number: C020102120018; Price: 0.01
C45 C46 C96 C97 C99 C100 C102 C103 C105 C107 C159 C160 C164 C261 C262 C264 C357-C360 C362 C363 C1013 C1015 C1017 C1019 C1037 C1046 C1047 = C-0603: DSC1: ±20%; DSC2: 10V; DSC3: X5R; ERP Number: 1010200076; ID: 71; Manufacture: 三星|国巨|村田; Part Name: 贴片电容; Part Number: C020102120071; Price: 0.05
C369 C1048 = C-0402: DSC1: ±5%; DSC2: 50V; DSC3: C0G; ID: 22; Manufacture: 三星|国巨|村田; Part Name: 贴片电容; Part Number: C020102120022; Price: 0.02
J18 = J-FPC-30P: DSC1: 30P; DSC2: 0.5mm间距; DSC3: 下接 翻盖 卧贴; DSC4: H=2mm; DSC5: 镀锡; DSC6: X05A20L30T(星坤); ID: 19; Part Name: FPC座; Part Number: J030102870078
J19 = J-FPC-24P: DSC1: 24P; DSC2: 0.5mm间距; DSC3: 上接 抽拉式 卧贴; DSC4: H=2mm; DSC5: 镀锡; DSC6: X05B20U24T(星坤); ID: 34; Part Name: FPC座; Part Number: J030102870021
J20 = J-FPC-30P_1: DSC1: 30P; ID: 19; Part Name: BTB座
R113 R136 R417 R445 R1168 R1169 R1200 = R-0402: DSC1: ±1%; DSC2: 1/16W; ERP Number: 1010200140; ID: 856; Part Name: 贴片电阻; Part Number: C011002080856; Price: 0.01
R123-R129 R172 R177 R192 R196-R199 R201-R203 R208 R210 R213 R215 R368-R372 R1171 R1207 R1208 = R-0402: DSC1: ±5%; DSC2: 1/16W; ERP Number: 1010200173; ID: 262; Part Name: 贴片电阻; Part Number: C011002080262; Price: 0.01
R130 R373-R375 R1065 R1068 = R-0402: DSC1: ±1%; DSC2: 1/16W; ERP Number: 1010200445; ID: 818; Part Name: 贴片电阻; Part Number: C011002080818; Price: 0.01
R132 R1066 R1069 = R-0402: DSC1: ±1%; DSC2: 1/16W; ID: 938; Part Name: 贴片电阻; Part Number: C011002080938; Price: 0.01
R133 R135 R137 R139 R1067 R1070 = R-0402: DSC1: ±5%; DSC2: 1/16W; ID: 335; Part Name: 贴片电阻; Part Number: C011002080335; Price: 0.01
R134 = R-0402: DSC1: ±1%; DSC2: 1/16W; ERP Number: 1010200327; ID: 900; Part Name: 贴片电阻; Part Number: C011002080900; Price: 0.01
R138 = R-0402: DSC1: ±1%; DSC2: 1/16W; ID: 882; Part Name: 贴片电阻; Part Number: C011002080882; Price: 0.01
R153-R156 R159 R160 R194 R401-R404 R416 R460 R1172 = R-0402: DSC1: ±5%; DSC2: 1/16W; ERP Number: 1010200100; ID: 217; Part Name: 贴片电阻; Part Number: C011002080217; Price: 0.01
R206 R363 R365 R1175 R1176 = RN_0402X4: DSC1: ±5%; DSC2: 1/16W; ID: 4; Part Name: 贴片排阻; Part Number: C010302090004; Price: 0.01
R1177 R1178 = R-0402: DSC1: ±1%; DSC2: 1/16W; ID: 638; Part Name: 贴片电阻; Part Number: C011002080638; Price: 0.01
R1179 R1180 = R-0402: DSC1: ±1%; DSC2: 1/16W; ERP Number: 1010200450; ID: 630; Part Name: 贴片电阻; Part Number: C011002080630; Price: 0.01
R456 R1181 = R-0402: DSC1: ±1%; DSC2: 1/16W; ERP Number: 1010200113; ID: 742; Part Name: 贴片电阻; Part Number: C011002080742; Price: 0.01
U11-U14 U71 U72 = U-ETA5050: DSC1: Vi=2.5-5.5V; DSC2: Vo=adj; DSC3: Io=500mA; DSC5: Iq=40uA; ID: 28; Manufacture: ETA; Part Name: LDO; Part Number: C070111104620; Solder: 推荐
C112 C113 C131 C133 C150 C152 = C-0402: DSC1: ±5%; DSC2: 50V; DSC3: C0G; ERP Number: 1010200152; ID: 40; Manufacture: 三星|国巨|村田; Part Name: 贴片电容; Part Number: C020102120040; Price: 0.01
C115 C116 C128 C129 C156 C158 = C-0402: DSC1: ±5%; DSC2: 50V; DSC3: C0G; ERP Number: 1010200091; ID: 27; Manufacture: 三星|国巨|村田; Part Name: 贴片电容; Part Number: C020102120027; Price: 0.02
C126 C531 C532 C1036 C1038 = C-0402: DSC1: ±10%; DSC2: 10V; DSC3: X5R; ERP Number: 1010200054; ID: 64; Manufacture: 三星|国巨|村田; Part Name: 贴片电容; Part Number: C020102120064; Price: 0.02
D33 D34 D80 = DI-TVS-SRV05-4: DSC1: 单向; DSC2: Vrwm=5V; DSC3: VBR=6V; DSC4: Vc=13V; DSC5: Ipp=3.5A; DSC6: Ppp=45W; DSC7: Cj=0.36pF; ERP Number: 1010800050; ID: 15; Manufacture: 伯恩半导体; Part Name: TVS; Part Number: C040602260015; Price: 0.21; Solder: 量产
J21 J22 = J-RJ45-HY911130A: DSC1: RJ45 8P插件，内置千兆变压器(商业级)  双灯 卧式 全包无弹片, / 16x21.3x13.5mm; DSC2: 通孔弯针; DSC3: G1159A01A-GY(华强盛); DSC4: HY911130A(汉仁); ID: 15; Part Name: RJ45; Part Number: J120105074660
L31 L32 = L-IND: DSC1: ±20%; DSC2: Isat=1.6A; DSC3: Irms=1.25A; DSC4: 260mΩ; DSC5: 2.5*2.0*1.2mm; DSC6: WPN252012H4R7MT(顺络); DSC7: FHD252012S-4R7MT(长江微电); DSC8: ZCRH252012-4.7uH-M(宗成); ID: 54; Manufacture: 宗成|长江微电|顺络; Part Name: 功率电感
R37 R38 R140-R142 R144 R145 R147-R149 R162-R169 R247 R248 = R-0402: DSC1: ±5%; DSC2: 1/16W; ERP Number: 1010200263; ID: 238; Part Name: 贴片电阻; Part Number: C011002080238; Price: 0.01
R150 R157 R189 R193 R218 R219 = R-0402: DSC1: ±5%; DSC2: 1/16W; ERP Number: 1010200226; ID: 296; Part Name: 贴片电阻; Part Number: C011002080296; Price: 0.01
R158 R183 R209 = R-0402: DSC1: ±1%; DSC2: 1/16W; ERP Number: 1010200324; ID: 785; Part Name: 贴片电阻; Part Number: C011002080785; Price: 0.01
R161 = R-0402: DSC1: ±5%; DSC2: 1/16W; ERP Number: 1010200104; ID: 303; Part Name: 贴片电阻; Part Number: C011002080303; Price: 0.01
R1064 = R-0805: DSC1: ±1%; DSC2: 1/8W; ERP Number: 1010200199; ID: 1,448; Part Name: 贴片电阻; Part Number: C011002081448; Price: 0.01
U15 = RL5877_0
XT2 XT3 = XTAL-4P: DSC1: 40Ω; DSC2: ±10ppm; DSC3: 12pF; DSC4: -40℃~+85℃; DSC5: 3.2*2.5mm 4P; ID: 6; Manufacture: 泰晶; Part Name: 贴片无源晶振; Part Number: C050102290006; Price: 0.48
C132 C143 = C-0402: DSC1: ±0.1PF; DSC2: 50V; DSC3: C0G; ERP Number: 1010200109; ID: 13; Manufacture: 三星|国巨|村田; Part Name: 贴片电容; Part Number: C020102120013; Price: 0.03
D35 D36 = DI-ESD-SRV05-4: DSC1: 单向; DSC2: Vrwm=5V; DSC3: VBR=6V; DSC4: Vc=13V; DSC5: Ipp=3.5A; DSC6: Ppp=45W; DSC7: Cj=0.36pF; ERP Number: 1010800050; ID: 15; Manufacture: 伯恩半导体; Part Name: TVS; Part Number: C040602260015; Price: 0.21; Solder: 量产
R170 R345-R350 = R-0402: DSC1: ±5%; DSC2: 1/16W; ERP Number: 1010200160; ID: 279; Part Name: 贴片电阻; Part Number: C011002080279; Price: 0.01
R171 = R-0402: DSC1: ±5%; DSC2: 1/16W; ID: 281; Part Name: 贴片电阻; Part Number: C011002080281; Price: 0.01
R35 R174-R176 R178-R182 R184 R185 R187 R188 R195 R200 R204 R205 R207 R211 R212 R216 R217 R220 R341 R1198 = R-0402: DSC1: ±5%; DSC2: 1/16W; ERP Number: 1010200177; ID: 320; Part Name: 贴片电阻; Part Number: C011002080320; Price: 0.01
R190 = R-0402: DSC1: ±5%; DSC2: 1/16W; ERP Number: 1010200103; ID: 353; Part Name: 贴片电阻; Part Number: C011002080353; Price: 0.01
R191 = R-0402: DSC1: ±5%; DSC2: 1/16W; ID: 309; Part Name: 贴片电阻; Part Number: C011002080309; Price: 0.01
U16 = U-RTL8211F-CG: DSC1: Ethernet Transceivers RGMII, RMII 10/100/1000 Base-T PHY; DSC2: QFN40，5mm×5mm，0.4mm Pitch; DSC3: -40℃~+85℃; ID: 59; Manufacture: REALTEK(瑞昱); Part Name: 以太网芯片; Part Number: C100105104678
J23 = J-RJ45-HR911105A_0: DSC1: RJ45 8P插件 内置百兆变压器(商业级)  双灯 卧式 全包无弹片, / 16x21.3x13.5mm; DSC2: 通孔弯针; DSC3: H1159A01A-GY(华强盛); DSC4: HR911105A(汉仁); ID: 4; Part Name: RJ45; Part Number: J120103060004
L11 L12 L29 = FB-0603: DSC1: 100Ω@100MHz; DSC2: 3A; DSC3: DCR=30mΩ; DSC4: 电源线; ERP Number: 1010200207; ID: 5; Manufacture: 顺络; Part Name: 贴片磁珠; Part Number: C060502370005; Price: 0.03
U17 = U-RTL8201F-VB-CG: DSC1: Physical Layer Transceivers IEEE 802.3, 10/100 Base-T/TX/FX PHY; DSC2: QFN32，5mm×5mm，0.5mm Pitch; DSC3: 0℃~+70℃; ERP Number: 1010100179; ID: 8; Manufacture: REALTEK(瑞昱); Part Name: 以太网芯片; Part Number: C100102490008
XT4 = XTAL-4P: DSC1: 40Ω; DSC2: ±10ppm; DSC3: 12pF; DSC4: -40℃~+85℃; DSC5: 3.2*2.5mm 4P; Manufacture: 泰晶; Part Name: 贴片无源晶振; Part Number: C050102290006; Price: 0.48
C289 C293 C295 C1040-C1042 = C-0603: DSC1: ±20%; DSC2: 10V; DSC3: X5R; ID: 83; Manufacture: 三星|国巨|村田; Part Name: 贴片电容; Part Number: C020107143899; Price: 0.18
C291 C292 C294 C301 = C-0402: DSC1: ±5%; DSC2: 50V; DSC3: C0G; ERP Number: 1010200087; ID: 33; Manufacture: 三星|国巨|村田; Part Name: 贴片电容; Part Number: C020102120033; Price: 0.01
C1039 = C-0402: DSC1: ±5%; DSC2: 50V; DSC3: C0G; ERP Number: 1010200213; ID: 36; Manufacture: 三星|国巨|村田; Part Name: 贴片电容; Part Number: C020102120036; Price: 0.01
D8 D9 D37-D42 = DI-ESD: DSC1: 双向; DSC2: Vdc=12V; DSC4: Vc=40V; DSC5: Cj=0.05pF; ID: 1; Manufacture: 硕凯; Part Name: ESD; Part Number: C040504013980; Price: 0.06; Solder: 推荐
J27 = J-M2_NGFF-M-KEY_1: DSC1: M2_NGFF-M座子,0.5mm Pitch,H=4.2mm; DSC2: 67P; DSC3: 贴片; DSC4: 91302-42-067RDM(Umaxconn); ID: 28; Part Name: 金手指连接器; Part Number: J050105094667
J42 = J-USB-9AFx2-DIP-W: DSC1: USB-3.0，插件弯脚，双层，蓝胶，有卷边，耐高温; DSC2: 17.5*14.5*15.5mm; DSC3: 通孔弯针; DSC5: JLX-USB-030（九龙熹）; ID: 14; Part Name: USB连接器; Part Number: J060111093946
L44 = L-IND: DSC1: ±20%; DSC2: Isat=3.6A; DSC3: Irms=3A; DSC4: 54mΩ; DSC5: 2.5*2.0*1.2mm; DSC6: WPN252012H1R0MT(顺络); DSC7: FHD252012S-1R0MT(长江微电); DSC8: ZCRH252012-1uH-M(宗成); ID: 52; Manufacture: 宗成|长江微电|顺络; Part Name: 功率电感
Q6 = N-MOS-Q: DSC1: Vds=30V; DSC2: Id=100mA; DSC3: Vgs(th)=1.5V; DSC4: Vgs=±20V; DSC5: pd=150mW; ERP Number: 1010800011; ID: 4; Manufacture: 先科; Part Name: N-MOS; Part Number: C030202190004; Price: 0.1
R253 = R-0402: DSC1: ±5%; DSC2: 1/16W; ERP Number: 1010200258; ID: 332; Part Name: 贴片电阻; Part Number: C011002080332; Price: 0.01
R258-R260 R342 R352 R353 R366 R405-R410 R1077 R1203-R1206 = R-0402: DSC1: ±1%; DSC2: 1/16W; ID: 413; Part Name: 贴片电阻; Part Number: C011002080413; Price: 0.01
R1170 = R-0402: DSC1: ±1%; DSC2: 1/16W; ID: 933; Part Name: 贴片电阻; Part Number: C011002080933; Price: 0.01
U6 U29 = U-SY6280AAC: DSC1: 低能耗电源开关; DSC2: 2.4-5.5V 2A; DSC3: 80mA; DSC4: -40~85℃; ID: 1; Manufacture: ETA; Part Name: 功率开关; Price: 0.42
U73 = U-ETA3417S2F: DSC1: Vi=2.6-7.0V; DSC2: Vo=0.6-7.0V; DSC3: Io=2.5A; DSC4: Vfb=0.6V; DSC6: 3MHz; DSC7: 同步降压; DSC8: 替代料：TI的TLV62569DBVR/矽力杰SY8089AAAC; ID: 43; Manufacture: ETA; Part Name: DCDC; Part Number: C070205183984; Solder: 量产
D194 D195 = DI-TVS-D: DSC1: 双向; DSC2: Vrwm=16V; DSC3: VBR=17.8V; DSC4: Vc=26V; DSC5: Ipp=15.4A; DSC6: Ppp=200W; ID: 28; Manufacture: 硕凯; Part Name: TVS
J44 = J-HDR-D-20: DSC1: 双排单塑; DSC2: 2x10; DSC3: 2.54mm脚距; DSC4: 通孔直针; DSC5: 针长11.5mm 3+2.5(H塑高)+6mm; DSC6: 黑胶; DSC7: X6521WV-2x10H-C30D60（星坤）; ID: 51; Part Name: 双排针; Part Number: J010102760104
J54-J56 = J-H-4P: DSC1: 4p; DSC2: 2.0mm间距; DSC3: 通孔180度直针; DSC4: 米黄色胶壳 耐高温; DSC5: JLX-PH20-4A（九龙熹）; DSC6: X2016WV-04-46SN(星坤); ID: 13; Part Name: PH; Part Number: J020302820003
L40-L43 L45 L46 = FB-0402: DSC1: 120Ω@100MHz; DSC2: 200mA; DSC3: DCR=400mΩ; DSC4: 低频信号; ERP Number: 1010200208; ID: 1; Manufacture: 顺络; Part Name: 贴片磁珠; Part Number: C060502370001; Price: 0.02
R425 R426 = R-0402: DSC1: ±1%; DSC2: 1/16W; ID: 778; Part Name: 贴片电阻; Part Number: C011002080778; Price: 0.01
R459 = R-0402: DSC1: ±5%; DSC2: 1/16W; ERP Number: 1010200096; ID: 328; Part Name: 贴片电阻; Part Number: C011002080328; Price: 0.01
R461 R462 = R-0603: DSC1: ±1%; DSC2: 1/10W; ID: 1,339; Part Name: 贴片电阻; Part Number: C011002081339; Price: 0.01
R1166 R1167 = R-0402: DSC1: ±1%; DSC2: 1/16W; ID: 552; Part Name: 贴片电阻; Part Number: C011002080552; Price: 0.01
U42 = U-SP3232EEN: DSC1: RS232 Transceiver up to 235kbps; DSC2: TSSOP-16，0.65mm Pitch; DSC3: -40℃~+85℃; ID: 73; Manufacture: Broadic; Part Name: RS232/RS485芯片; Part Number: C100305124693; Price: 0.91
U43 = U-TJA1057GT-3J: DSC1: CAN Transceiver, 5Mbps; DSC2: SOIC-8_150mil，1.27mm Pitch; DSC3: -40℃~+85℃; ID: 76; Manufacture: 芯力特; Part Name: CAN芯片; Part Number: C100405124698; Price: 4.6

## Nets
GND: C45.2 C46.2 C94.1 C95.1 C96.1 C97.1 C98.1 C99.1 C100.1 C101.1 C102.1 C103.1 C104.1 C105.1 C107.1 C108.1 C112.2 C113.2 C114.1 C115.2 C116.2 C126.2 C128.1 C129.1 C130.1 C131.1 C132.1 C133.1 C143.1 C147.1 C150.2 C151.1 C152.1 C155.1 C156.2 C158.1 C159.1 C160.1 C163.1 C164.1 C166.1 C261.2 C262.2 C264.1 C265.1 C266.1 C267.1 C268.1 C288.1 C289.1 C291.1 C292.1 C293.1 C294.1 C295.1 C301.1 C318.1 C320.1 C321.1 C322.1 C323.1 C324.1 C325.1 C326.1 C327.1 C328.1 C329.1 C330.1 C331.1 C332.1 C333.1 C334.1 C335.1 C336.1 C337.1 C338.1 C339.1 C340.1 C341.1 C347.1 C348.1 C349.1 C350.1 C351.1 C352.1 C357.1 C358.1 C359.1 C360.1 C361.1 C362.1 C363.1 C364.1 C528.2 C530.2 C531.2 C532.2 C533.2 C1013.1 C1014.1 C1015.1 C1016.1 C1017.1 C1018.1 C1019.1 C1020.1 C1022.1 C1023.1 C1024.1 C1025.1 C1026.1 C1027.1 C1028.1 C1029.1 C1030.1 C1036.1 C1037.1 C1038.1 C1040.1 C1041.1 C1042.1 C1044.1 C1045.1 C1046.1 C1047.1 D8.1(I/O2) D9.2(I/O1) D33.2 D34.2 D35.2 D36.2 D37.1(I/O2) D38.1(I/O2) D39.1(I/O2) D40.1(I/O2) D41.1(I/O2) D42.1(I/O2) D80.2 D194.C(I/O1) D195.C(I/O1) J18.1 J18.4 J18.7 J18.10 J18.13 J18.16 J18.18 J18.23 J18.25 J18.31 J18.32 J19.10 J19.13 J19.16 J19.19 J19.22 J19.25 J19.26 J20.6 J20.12 J20.16 J20.19 J20.27 J20.29 J20.30 J20.31 J20.32 J20.33 J20.34 J21.10(GND) J22.10(GND) J23.8(P8) J27.1(GND) J27.3(GND) J27.9(GND) J27.15(GND) J27.21(GND) J27.27(GND) J27.33(GND) J27.39(GND) J27.45(GND) J27.51(GND) J27.57(GND) J27.71(GND) J27.73(GND) J27.75(GND) J27.G1(EHT1) J27.G2(EHT2) J27.G3(G4) J27.G4(G3) J42.4(GND1) J42.7(GND2) J42.13(GND3) J42.16(GND4) J42.19(SHELL1) J42.20(SHELL2) J42.21(SHELL3) J42.22(SHELL4) J44.19 J54.4 J55.4 J56.4 Q6.2(SOURCE) R35.2 R133.1 R135.1 R137.1 R139.1 R158.1 R171.1 R174.1 R176.1 R179.1 R180.1 R181.1 R183.1 R184.1 R187.1 R193.2 R200.1 R209.2 R211.2 R216.2 R218.1 R220.2 R253.1 R341.2 R459.2 R1067.1 R1070.1 R1169.1 R1177.2 R1178.2 R1198.1 U6.2(GND) U11.2(GND) U12.2(GND) U13.2(GND) U14.2(GND) U15.33(GND) U16.41(E_Pad) U17.33(E-Pad) U29.2(GND) U42.15(GND) U43.2(GND) U71.2(GND) U72.2(GND) U73.2(GND) XT2.2 XT2.4 XT3.2 XT3.4 XT4.2 XT4.4 ; also on sheet 1 2 3 4 5 12 13 14
GND_EARTH: J21.SH1 J21.SH2 J22.SH1 J22.SH2 J23.13(P13) J23.14(P14) ; also on sheet 2
VCC1V2_DVP: C103.2 C104.2 C1023.2 C1030.2 C1048.2 J18.28 J20.22 R136.2 U13.5(VOUT)
VCC1V5_DVP: C107.2 C108.2 C369.2 C1026.2 J19.3 R138.2 U14.5(VOUT)
VCC1V8_DVP: C100.2 C101.2 C1024.2 C1027.2 C1029.2 J18.27 J19.4 J20.24 R113.2 R134.2 R417.2 U12.5(VOUT)
VCC2V8_DVP: C96.2 C98.2 C1028.2 J20.8 J20.25 R132.2 U11.5(VOUT)
VCC2V8_DVP1: C1015.2 C1016.2 C1022.2 J19.1 J19.2 R1066.2 U71.5(VOUT)
VCC2V8_DVP2: C1019.2 C1020.2 C1025.2 J18.24 J18.29 R1069.2 U72.5(VOUT)
VCC3V3_E: C1039.2 C1040.2 C1041.2 C1042.2 L29.1 L44.2 R1170.2
VCC3V3_PHY0: C333.2 C334.2 C335.2 C359.2 C360.2 R175.2 R189.2 R190.2 R194.2 U16.11(AVDD33) U16.29(DVDD33) U16.40(AVDD33)
VCC3V3_PHY2: C325.2 C326.2 C327.2 C363.2 R150.2 R156.1 R157.2 R160.2 R161.1 U15.11(AVDD33(NC)) U15.23(VDDREG(DVDD33)) U15.32(AVDD33)
VCC5V0_HUB2: C45.1 J42.10(VBUS2) U6.1(VOUT)
VCC5V_SYS: C46.1 C262.1 C1037.2 C1038.2 C1044.2 R1168.2 U6.5(IN) U29.5(IN) U73.4(VIN) ; also on sheet 1 2 3 4
VCC_3V3: C97.2 C99.2 C102.2 C105.2 C1013.2 C1017.2 C1036.2 L12.1 R160.1 R194.1 R425.1 R426.1 R460.2 R1077.1 R1181.2 U11.1(VIN) U12.1(VIN) U13.1(VIN) U14.1(VIN) U42.16(VCC) U71.1(VIN) U72.1(VIN) ; also on sheet 1 2 3 5 12 14
VCC_M2: C289.2 C291.2 C292.2 C293.2 C294.2 C295.2 C301.2 C348.2 C349.2 C350.2 C351.2 C352.2 J27.2(3.3V) J27.4(3.3V) J27.12(3.3V) J27.14(3.3V) J27.16(3.3V) J27.18(3.3V) J27.70(3.3V) J27.72(3.3V) J27.74(3.3V) L29.2
VCC_OUT: C264.2 C1046.2 C1047.2 J44.1 J54.1 J55.1 J56.1 R366.2 R1077.2
VCC_RMII: C159.2 C164.2 C338.2 L11.1 L12.2 R195.2 R204.2 R205.1 R207.1 R212.2 R217.2 R219.1 R1200.2 U17.14(DVDD33)
VCCA_RMII: C160.2 C336.2 C337.2 L11.2 U17.7(AVDD33_1) U17.30(AVDD33_2)
VCCIO_PHY0: C358.2 C361.2 R178.2 R182.2 R185.2 R188.2 R191.2 U16.28(DVDD_RG)
VDD10_PHY0: C328.2 C329.2 C330.2 C331.2 C332.2 C357.2 L31.2 U16.3(AVDD10) U16.8(AVDD10) U16.21(DVDD10) U16.38(AVDD10)
VDD10_PHY2: C320.2 C362.2 L32.2 R159.1 R1064.2
VDD10_RTL: C126.1 C321.2 C322.2 C323.2 C324.2 R159.2 U15.3(AVDD10(NC)) U15.8(AVDD10_0) U15.22(DVDD10(NC)) U15.30(AVDD10_1)
VDD_5V: C532.1 R366.1 U43.3(VCC) ; also on sheet 1 5 12
ADC0: J44.10 R350.2
ADC1: J44.12 R349.2
ADC2: J44.14 R348.2
ADC3: J44.16 R347.2
ADC4: J44.18 R346.2
ADC5: J44.20 R345.2
AF-PWDN: J20.26 R416.2
CAM_CLK0_OUT_M1: R123.1 ; also on sheet 2
CAM_CLK2_OUT: R1179.1 ; also on sheet 2
CAM_CLK3_OUT: R1180.1 ; also on sheet 2
CAN0_H: D194.A(I/O2) J56.2 L45.2
CAN0_L: D195.A(I/O2) J56.3 L46.2
CAN0_RX_M2: R1208.2 U43.4(RXD)
CAN0_STB_IO: R459.1 U43.8(S)
CAN0_TX_M2: R1207.2 U43.1(TXD)
CAN0H: L45.1 R462.1 U43.7(CANH)
CAN0L: L46.1 R461.1 U43.6(CANL)
CIF1_SCL: J18.21 R126.2
CIF1_SDA: J18.22 R127.2
CIF2_RST: C288.2 J20.5 R372.2 R417.1
CIF2_RST_L: R372.1 ; also on sheet 2
CIF2_SCL: J19.7 J20.21 R128.2
CIF2_SDA: J19.8 J20.23 R129.2
CIF_EN: R130.1 R373.1 R374.1 R375.1 R1065.1 R1068.1 R1172.2 R1181.1
CIF_PDN: J18.19 J19.6 J20.20 R124.2 R416.1
CIF_PDN_L: R124.1 ; also on sheet 2
CIF_PWREN_H: R1172.1 ; also on sheet 2
CIF_RST: C94.2 J18.20 J19.5 R113.1 R125.2
CIF_RST_L: R125.1 ; also on sheet 2
CKXTALIN: C156.1 U17.32(CKXTAL-IN) XT4.3
CKXTALOUT: C158.2 U17.31(CKXTAL-OUT) XT4.1
CLKREQB: R155.2 U15.12(CLKREQB)
CSI0_MCLK: C95.2 J20.14 R123.2
CSI2_MCLK: J19.9 R1177.1 R1179.2
CSI3_MCLK: J18.17 R1178.1 R1180.2
GMAC0_TXCLK_: C132.2 R177.2 U16.20(TXC)
GMAC1_RSTn: C364.2 R172.2 R190.1 U16.12(PHYRSTB)
GMAC1_RSTn_GPIO0_A6_d: R172.1 ; also on sheet 2
HUB_DM2: R37.1 ; also on sheet 3
HUB_DM2_2: D8.2(I/O1) J42.11(2D-) R37.2
HUB_DP2: R38.1 ; also on sheet 3
HUB_DP2_2: D9.1(I/O2) J42.12(2D+) R38.2
I2C1_SCL_M1: R128.1 ; also on sheet 2
I2C1_SDA_M1: R129.1 ; also on sheet 2
I2C2_SCL_M1: R126.1 ; also on sheet 2
I2C2_SDA_M1: R127.1 ; also on sheet 2
I2C5_SCL_M0/UART9_TX_M1: J44.15 R365.6 R425.2
I2C5_SDA_M0/UART9_RX_M1: J44.17 R365.5 R426.2
ISOLATEB: R156.2 U15.20(ISOLATEB)
LAN0_A+: D36.6 J22.2(MDI_0+) R169.2
LAN0_A-: D36.1 J22.3(MDI_0-) R168.2
LAN0_B+: D36.3 J22.4(MDI_1+) R167.2
LAN0_B-: D36.4 J22.7(MDI_1-) R166.2
LAN0_C+: D35.6 J22.5(MDI_2+) R165.2
LAN0_C-: D35.1 J22.6(MDI_2-) R164.2
LAN0_D+: D35.3 J22.8(MDI_3+) R163.2
LAN0_D-: D35.4 J22.9(MDI_3-) R162.2
LANWAKEB: R154.2 R161.2 U15.21(LANWAKEB)
LED0/PHYAD0: C152.2 J23.11(Y-) R205.2 U17.24(LED0/PHYAD0/PMEB)
LED1/GPO: C112.1 J21.13(Y_LED-) U15.26(LED1/GPO)
LED1/PHYAD1: C150.1 J23.9(G+) R200.2 U17.25(LED1/PHYAD1)
LED2/LED1: C113.1 J21.12(G_LED-) U15.25(LED2(LED1))
MAC_MDC_: C151.2 R203.2 U17.22(MDC)
MAC_MDIO: R202.2 R207.2 U17.23(MDIO)
MIPI_CSI1_RX0_D2N: J19.11 R1175.5
MIPI_CSI1_RX0_D2P: J19.12 R1175.6
MIPI_CSI1_RX0_D3N: J19.14 R1175.7
MIPI_CSI1_RX0_D3P: J19.15 R1175.8
MIPI_CSI2_RX0_D2N: J18.11 R1176.8
MIPI_CSI2_RX0_D2P: J18.12 R1176.7
MIPI_CSI2_RX0_D3N: J18.14 R1176.6
MIPI_CSI2_RX0_D3P: J18.15 R1176.5
MIPI_CSI_RX0_CLK0N: J18.5 ; also on sheet 2
MIPI_CSI_RX0_CLK0P: J18.6 ; also on sheet 2
MIPI_CSI_RX0_CLK1N: J19.17 ; also on sheet 2
MIPI_CSI_RX0_CLK1P: J19.18 ; also on sheet 2
MIPI_CSI_RX0_D0N: J18.2 ; also on sheet 2
MIPI_CSI_RX0_D0P: J18.3 ; also on sheet 2
MIPI_CSI_RX0_D1N: J18.8 ; also on sheet 2
MIPI_CSI_RX0_D1P: J18.9 ; also on sheet 2
MIPI_CSI_RX0_D2N: R1175.4 R1176.1 ; also on sheet 2
MIPI_CSI_RX0_D2P: R1175.3 R1176.2 ; also on sheet 2
MIPI_CSI_RX0_D3N: R1175.2 R1176.3 ; also on sheet 2
MIPI_CSI_RX0_D3P: R1175.1 R1176.4 ; also on sheet 2
MIPI_CSI_RX1_CLK0N: J20.17 ; also on sheet 2
MIPI_CSI_RX1_CLK0P: J20.15 ; also on sheet 2
MIPI_CSI_RX1_D0N: J20.13 ; also on sheet 2
MIPI_CSI_RX1_D0P: J20.11 ; also on sheet 2
MIPI_CSI_RX1_D1N: J20.9 ; also on sheet 2
MIPI_CSI_RX1_D1P: J20.7 ; also on sheet 2
MIPI_CSI_RX1_D2N: J20.3 ; also on sheet 2
MIPI_CSI_RX1_D2P: J20.1 ; also on sheet 2
MIPI_CSI_RX1_D3N: J20.4 ; also on sheet 2
MIPI_CSI_RX1_D3P: J20.2 ; also on sheet 2
PCIE20_0_TXN: C317.2 U15.14(HSIN)
PCIE20_0_TXP: C319.2 U15.13(HSIP)
PCIE20_32KHz: J27.68(SUSCLK(32kHz)(I)(3.3V)) R342.2
PCIE20_CLKREQN: J27.52(PCIE_CLKREQ#(IO)(3.3V)) R258.2
PCIE20_CLKREQN_M1: R155.1 R258.1 ; also on sheet 2 12
PCIE20_PERSTN: J27.50(PCIE_PERST#(I)(3.3V)) R260.2
PCIE20_PERSTN_M1: R153.1 R260.1 ; also on sheet 2 12
PCIE20_REFCLKN: R404.1 R408.1 ; also on sheet 2
PCIE20_REFCLKN_: J27.53(REFCLKN) R408.2
PCIE20_REFCLKP: R403.1 R407.1 ; also on sheet 2
PCIE20_REFCLKP_: J27.55(REFCLKP) R407.2
PCIE20_RXDN: J27.41(PETn0/SATA-B+) R406.2
PCIE20_RXDP: J27.43(PETp0/SATA-B-) R405.2
PCIE20_TXDN: C354.1 J27.47(PERn0/SATA-A-)
PCIE20_TXDP: C353.1 J27.49(PERp0/SATA-A+)
PCIE20_WAKEN: J27.54(PCIE_PEWake#(IO)(3.3V)) R259.2
PCIE20_WAKEN_M1: R154.1 R259.1 ; also on sheet 2 12
PCIE_0_RXN: R402.2 U15.18(HSON)
PCIE_0_RXP: R401.2 U15.17(HSOP)
PERSTB: C318.2 R153.2 U15.19(PERSTB)
PHY0_CLKOUT125: R170.2 U16.35(CLKOUT)
PHY0_LED0/CFG_EXT: R174.2 U16.32(LED0/CFG_EXT)
PHY0_LED1/CFG_LDO0: C133.2 J22.14(Y_LED+) R176.2 U16.33(LED1/CFG_LDO0)
PHY0_LED2/CFG_LDO1: C131.2 J22.12(G_LED-) R175.1 U16.34(LED2/CFG_LDO1)
PHY0_MDI0+: R169.1 U16.1(MDI[0]+)
PHY0_MDI0-: R168.1 U16.2(MDI[0]-)
PHY0_MDI1+: R167.1 U16.4(MDI[1]+)
PHY0_MDI1-: R166.1 U16.5(MDI[1]-)
PHY0_MDI2+: R165.1 U16.6(MDI[2]+)
PHY0_MDI2-: R164.1 U16.7(MDI[2]-)
PHY0_MDI3+: R163.1 U16.9(MDI[3]+)
PHY0_MDI3-: R162.1 U16.10(MDI[3]-)
PHY0_REG_OUT: L31.1 U16.30(REG_OUT)
PHY0_RXCLK/PHYAD1: R179.2 R192.1 U16.27(RXC/PHYAD1)
PHY0_XTALIN: C129.2 U16.36(XTAL_IN) XT3.3
PHY0_XTALOUT: C128.2 U16.37(XTAL_OUT/EXT_CLK) XT3.1
PHY2_MDI0+: R145.1 U15.1(MDIP0)
PHY2_MDI0-: R144.1 U15.2(MDIN0)
PHY2_MDI1+: R149.1 U15.4(MDIP1)
PHY2_MDI1-: R148.1 U15.5(MDIN1)
PHY2_MDI2+: R142.1 U15.6(MDIP2(NC))
PHY2_MDI2-: R141.1 U15.7(MDIN2(NC))
PHY2_MDI3+: R147.1 U15.9(MDIP3(NC))
PHY2_MDI3-: R140.1 U15.10(MDIN3(NC))
PHY2_MDI_0+: D34.4 J21.2(MDI_0+) R145.2
PHY2_MDI_0-: D34.3 J21.3(MDI_0-) R144.2
PHY2_MDI_1+: D34.6 J21.4(MDI_1+) R149.2
PHY2_MDI_1-: D34.1 J21.7(MDI_1-) R148.2
PHY2_MDI_2+: D33.4 J21.5(MDI_2+) R142.2
PHY2_MDI_2-: D33.3 J21.6(MDI_2-) R141.2
PHY2_MDI_3+: D33.6 J21.8(MDI_3+) R147.2
PHY2_MDI_3-: D33.1 J21.9(MDI_3-) R140.2
PHY2_REG_OUT: L32.1 R1064.1 U15.24(REGOUT(NC))
PHY2_XTALIN: C116.1 U15.28(CKXTAL1) XT2.3
PHY2_XTALOUT: C115.1 U15.29(CKXTAL2) XT2.1
PHY_INT: R195.1 U17.11(RXD2/INTB)
PMIC_32KOUT_WIFI: R342.1 ; also on sheet 2 13
PMIC_EXT_EN: R1171.1 ; also on sheet 1 2
REFCLKN_100M_RJ45: R404.2 U15.16(REFCLK_N)
REFCLKP_100M_RJ45: R403.2 U15.15(REFCLK_P)
RGMII_CLK_M0: C130.2 R170.1 R171.2 ; also on sheet 2
RGMII_MDC_M0: U16.13(MDC) ; also on sheet 2
RGMII_MDIO_M0: R191.1 U16.14(MDIO) ; also on sheet 2
RGMII_RXCLK_M0: C143.2 R192.2 ; also on sheet 2
RGMII_RXD0_M0: R181.2 R182.1 U16.25(RXD0/RXDLY) ; also on sheet 2
RGMII_RXD1_M0: R184.2 R185.1 U16.24(RXD1/TXDLY) ; also on sheet 2
RGMII_RXD2_M0: R187.2 R188.1 U16.23(RXD2/PLLOFF) ; also on sheet 2
RGMII_RXD3_M0: R178.1 U16.22(RXD3/PHYAD0) ; also on sheet 2
RGMII_RXDV_M0: R180.2 U16.26(RXCTL/PHYAD2) ; also on sheet 2
RGMII_TXCLK_M0: R177.1 ; also on sheet 2
RGMII_TXD0_M0: U16.18(TXD0) ; also on sheet 2
RGMII_TXD1_M0: U16.17(TXD1) ; also on sheet 2
RGMII_TXD2_M0: U16.16(TXD2) ; also on sheet 2
RGMII_TXD3_M0: U16.15(TXD3) ; also on sheet 2
RGMII_TXEN_M0: U16.19(TXCTL) ; also on sheet 2
RMII_CLK: C155.2 R213.1 ; also on sheet 2
RMII_CLK_: R213.2 U17.15(TXC)
RMII_CLK_CTL: R216.1 U17.12(RXD3/CLK_CTL)
RMII_CRS_DV: R215.1 R1198.2 ; also on sheet 2
RMII_CRS_DVALID: R215.2 U17.26(CRS/CRS_DV)
RMII_MDC: R203.1 ; also on sheet 2
RMII_MDIO: R202.1 ; also on sheet 2
RMII_RST_: C340.2 R204.1 R208.2 U17.21(PHYRSTB)
RMII_RSTn: R208.1 ; also on sheet 2
RMII_RXD0: R197.2 ; also on sheet 2
RMII_RXD1: R196.2 ; also on sheet 2
RMII_RXER: R210.1 ; also on sheet 2
RMII_TXD0: R199.1 ; also on sheet 2
RMII_TXD0_: R199.2 U17.16(TXD0)
RMII_TXD1: R198.1 ; also on sheet 2
RMII_TXD1_: R198.2 U17.17(TXD1)
RMII_TXEN: R201.1 ; also on sheet 2
RMII_TXEN_: R201.2 U17.20(TXEN)
RN: R206.1 U17.6(MDI1-)
RP: R206.2 U17.5(MDI1+)
RS232_RX6: L42.1 U42.13(R1IN)
RS232_RX6_: J55.2 L42.2
RS232_RX8: L41.1 U42.8(R2IN)
RS232_RX8_: J54.2 L41.2
RS232_TX6: L43.1 U42.14(T1OUT)
RS232_TX6_: J55.3 L43.2
RS232_TX8: L40.1 U42.7(T2OUT)
RS232_TX8_: J54.3 L40.2
RSET0: R183.2 U16.39(RSET)
RSET2: R158.2 U15.31(RSET)
RXD0: R197.1 U17.9(RXD0)
RXD1: R196.1 R211.1 R212.1 U17.10(RXD1)
RXDV: R217.1 U17.8(RXDV)
RXER/FXEN: R210.2 R220.1 U17.28(RXER/FXEN)
RXN: D80.4 J23.6(P6) R206.8
RXP: D80.3 J23.3(P3) R206.7
SARADC1_IN0: R350.1 ; also on sheet 2
SARADC1_IN1: R349.1 ; also on sheet 2
SARADC1_IN2: R348.1 ; also on sheet 2
SARADC1_IN3: R347.1 ; also on sheet 2
SARADC1_IN4: R346.1 ; also on sheet 2
SARADC1_IN5: R345.1 ; also on sheet 2
SPI0_CLK_M0: R363.2 ; also on sheet 2
SPI0_CLK_M0/PWM0_M0: J44.4 R363.7
SPI0_CSN0_M0: R363.1 ; also on sheet 2
SPI0_CSN0_M0/PWM5_M0: J44.2 R363.8
SPI0_MISO_M0: R363.4 ; also on sheet 2
SPI0_MISO_M0/PWM2_M0: J44.8 R363.5
SPI0_MOSI_M0: R363.3 ; also on sheet 2
SPI0_MOSI_M0/PWM1_M0: J44.6 R363.6
TN: R206.3 U17.4(MDI0-)
TP: R206.4 U17.3(MDI0+)
TXN: D80.6 J23.2(P2) R206.6
TXP: D80.1 J23.1(P1) R206.5
UART4_RX: J44.5 R369.2
UART4_RX_M0: R369.1 ; also on sheet 2
UART4_TX: J44.3 R368.2
UART4_TX_M0: R368.1 ; also on sheet 2
UART6_RX: J44.9 R371.2 R1167.1
UART6_RX_: R1167.2 U42.12(R1OUT)
UART6_RX_M0: R371.1 R1208.1 ; also on sheet 2
UART6_TX: J44.7 R370.2 U42.11(T1IN)
UART6_TX_M0: R370.1 R1207.1 ; also on sheet 2
UART8_RX: J44.13 R365.7 R1166.1
UART8_RX_: R1166.2 U42.9(R2OUT)
UART8_RX_M0: R365.2 ; also on sheet 2
UART8_TX: J44.11 R365.8 U42.10(T2IN)
UART8_TX_M0: R365.1 ; also on sheet 2
UART9_RX_M1: R365.4 ; also on sheet 2
UART9_TX_M1: R365.3 ; also on sheet 2
USB30_OTG0_DM: R247.1 ; also on sheet 2
USB30_OTG0_DP: R248.1 ; also on sheet 2
USB30_OTG0_ID: Q6.3(DRAIN) ; also on sheet 2
USB30_OTG0_SSRXN/PCIE20_RXDN: R406.1 R1204.1 ; also on sheet 2
USB30_OTG0_SSRXP/PCIE20_RXDP: R405.1 R1203.1 ; also on sheet 2
USB30_OTG0_SSTXN/PCIE20_TXDN: C354.2 R1205.1 ; also on sheet 2
USB30_OTG0_SSTXP/PCIE20_TXDP: C353.2 R1206.1 ; also on sheet 2
USB30_OTG0_VBUSDET: C347.2 R253.2 R353.2 R445.1 ; also on sheet 2
USB_HOST2_PWREN_H: R1168.1 U6.4(EN)
USB_OTG: C261.1 J42.1(VBUS1) R445.2 U29.1(VOUT)
USB_OTG_DET_GPIO0_C0_d: R353.1 ; also on sheet 2
USB_OTG_DM: D37.2(I/O1) J42.2(1D-) R247.2
USB_OTG_DP: D38.2(I/O1) J42.3(1D+) R248.2
USB_OTG_PWREN: R352.1 ; also on sheet 2
USB_OTG_PWREN_H: R352.2 R456.1 U29.4(EN)
USB_OTG_SSRXN: D42.2(I/O1) J42.5(RX1-) R410.2
USB_OTG_SSRXP: D41.2(I/O1) J42.6(RX1+) R409.2
USB_OTG_SSTXN: C346.1 D40.2(I/O1) J42.8(TX1-)
USB_OTG_SSTXP: C345.1 D39.2(I/O1) J42.9(TX1+)
USB_PCIE_RXN: R402.1 R410.1 R1204.2
USB_PCIE_RXP: R401.1 R409.1 R1203.2
USB_PCIE_TXN: C317.1 C346.2 R1205.2
USB_PCIE_TXP: C319.1 C345.2 R1206.2
N19354508: C1048.1 R136.1 R137.2 U13.4(ADJ)
N19356461: R132.1 R133.2 U11.4(ADJ)
N19357233: R134.1 R135.2 U12.4(ADJ)
N19411583: J21.14(Y_LED+) R157.1
N20425490: J21.11(G_LED+) R150.1
N69917404: C369.1 R138.1 R139.2 U14.4(ADJ)
N69923813: C114.2 J21.1(CT1/2/3/4)
N69957333: C147.2 J22.1(CT1/2/3/4)
N69957443: J22.11(G_LED+) R189.1
N69960536: J22.13(Y_LED-) R193.1
N69961030: C163.2 J23.4(P4)
N69961588: C166.2 J23.5(P5)
N69966336: J23.12(Y+) R219.2
N70024964: R341.1 U29.3(OCB)
N70036634: Q6.1(GATE) R456.2
N70058734: R35.1 U6.3(OCB)
N70074623: C265.2 R130.2 U11.3(EN)
N70074833: C266.2 R373.2 U12.3(EN)
N70075015: C267.2 R374.2 U13.3(EN)
N70075198: C268.2 R375.2 U14.3(EN)
N70130938: C339.2 U17.29(DVDD10OUT)
N70177512: R1066.1 R1067.2 U71.4(ADJ)
N70177574: C1014.2 R1065.2 U71.3(EN)
N70177973: R1069.1 R1070.2 U72.4(ADJ)
N70178035: C1018.2 R1068.2 U72.3(EN)
N70209679: C529.1 U42.1(C1+)
N70209681: C529.2 U42.3(C1-)
N70209685: C527.1 U42.4(C2+)
N70209687: C527.2 U42.5(C2-)
N70209691: C530.1 U42.2(V+)
N70209695: C528.1 U42.6(V-)
N70210897: C1039.1 R1169.2 R1170.1 U73.5(FB)
N70210968: L44.1 U73.3(SW)
N70211090: C1045.2 R1171.2 U73.1(EN)
N70266506: J23.10(G-) R218.2
N70266836: R1200.1 U17.19(TXD3)
N70310222: C533.1 R461.2 R462.2
N70310339: C531.1 R460.1 U43.5(VIO/NC)
N76747942: R209.1 U17.1(RSET)
N76750177: C341.2 U17.2(AVDD100UT)

Not connected (* = marked no-connect by the designer): D33 5*; D34 5*; D35 5*; D36 5*; D80 5*; J18 26 30; J19 20* 21* 23* 24*; J20 10* 18* 28*; J23 7(P7)* 15* 16*; J27 5(PETn3)* 6(N/C_06)* 7(PETp3)* 8(N/C_08)* 10(DAS/DSS#(O)(OD))* 11(PERn3)* 13(PERp3)* 17(PETn2)* 19(PETp2)* 20(N/C)* 22(N/C)* 23(PERn2)* 24(N/C)* 25(PERp2)* 26(N/C)* 28(N/C)* 29(PETn1)* 30(N/C)* 31(PETp1)* 32(N/C)* 34(N/C)* 35(PERn1)* 36(N/C)* 37(PERp1)* 38(DEVSLP(I)(3.3V)) 40(N/C)* 42(N/C)* 44(N/C)* 46(N/C)* 48(N/C)* 56(Reserved/MFG_Data)* 58(Reserved/MFG_Clock)* 67(N/C)* 69(PEDET(NC-PCIe)(GND-SATA))* 77(HOLE2) 78(HOLE1); J42 14(RX2-)* 15(RX+)* 17(TX2-)* 18(TX2+)*; U15 27(LED0); U16 31(INTB/PMEB); U17 13(RXC) 18(TXD2) 27(COL)

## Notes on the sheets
sheet 6
- MIPI_CSI 2lanes
- MIPI_CSI 4lanes
sheet 7
- PCIE TO RJ45
- USB3.0/M.2-KEY/1000M复用功能
- M.2-KEY/1000M复用功能
- 3.3V IO
- ISOLATEB :Isolate Pin(Active Low,
  1.8V/3,3V compatible input)Used
  to isolate the RTL8111HS from the
  PCI Express bus,The RTL8111HS will
  not drive its PCI Express input as
  long as the Isolate pin is asserted.
- LANWAKEB:Power Management Event
  (Open Drain;Active Low,1.8V/3.3V
  compatible input/output mode
  with a weak external pull resistor)
- Reserve for EMI.
- Reserve for EMI.
- RTL8111HS:Switching Regulator
                     1.0V Output.
- RTL8111HS：Switching Regulator 1.0V Output.
  RTL8111H:  LDO Regulator 1.0V Output.
- Close to PIN3,8,30
- Close to PIN11,23,32
- Close to PIN22
sheet 8
- Giga PHY1
- RGMII Power Source
- CFG_EXT
- CFG_LDO[1:0]
- External 3.3V
- 1'b1
- 2'b00
- External 1.8V
- 1'b1
- 2'b10
- Internal 1.8V (default)
- 1'b0
- 2'b10
- VCCIO_PHY0
- 3.3Vpp
- MAC <----- PHY
- Reserve for EMI.
- VCC_PHY0_IO Voltage Config
- Close to SOC
- Reserve for EMI.
- PHY Address Config
- PHY Address
- PHYAD[2:0]
- 1 (default)
- 3'b001
- Pull-up for additional 2ns delay to RXC for data latching
- Pull-up for additional 2ns delay to TXC for data latching
- Pull-up to disable PLL @ ALDPS mode(Low power mode)
- Close to PIN21
- Close to PIN30
- RTL8211F-CG(SW Mode)
- RTL8211FI-CG(SW Mode)Industrial
- Close to PIN3,8,38
- RTL8211F-CG(SW Mode)
- RTL8211FI-CG(SW Mode)Industrial
- Note:
- According to the actual
  choice of mounted
  Cannot be mounted
  at the same time
- PHYRSTB is 3.3V IO
- Close to PIN28
- Close to PIN11,40
- Close to PHY
- Close to PIN29
sheet 9
- CAN
- RS232
sheet 10
- USB3.0/M.2-KEY/1000M复用功能
- 和UART复用功能
- USB3.0/M.2-KEY/1000M复用功能
- VCC3V3_E
- EN>1.2V
- USB3.0/M.2-KEY/1000M复用功能
- M.2-KEY/1000M复用功能
sheet 11
- CLOSE TO CPU
- PHY Address/LED
- CLOSE TO PHY
- WOL/LED0 Selection
- Pull Low for LED0 Mode(default)
  Pull High for WOL Mode
- WOL:Wake-on-LAN
- 拉高可以进行网络唤醒功能
- RMII REF_CLK direction
- RMII_POWER
- Pull Low for RMII REF_CLK Output mode
  Pull High for RMII REF_CLK Input mode
- MII/RMII Selection
- Pull High for RMII mode(default)
- UTP / Fiber Selection
- Pull Low for UTP Mode(default)
  Pull High for Fiber Mode
